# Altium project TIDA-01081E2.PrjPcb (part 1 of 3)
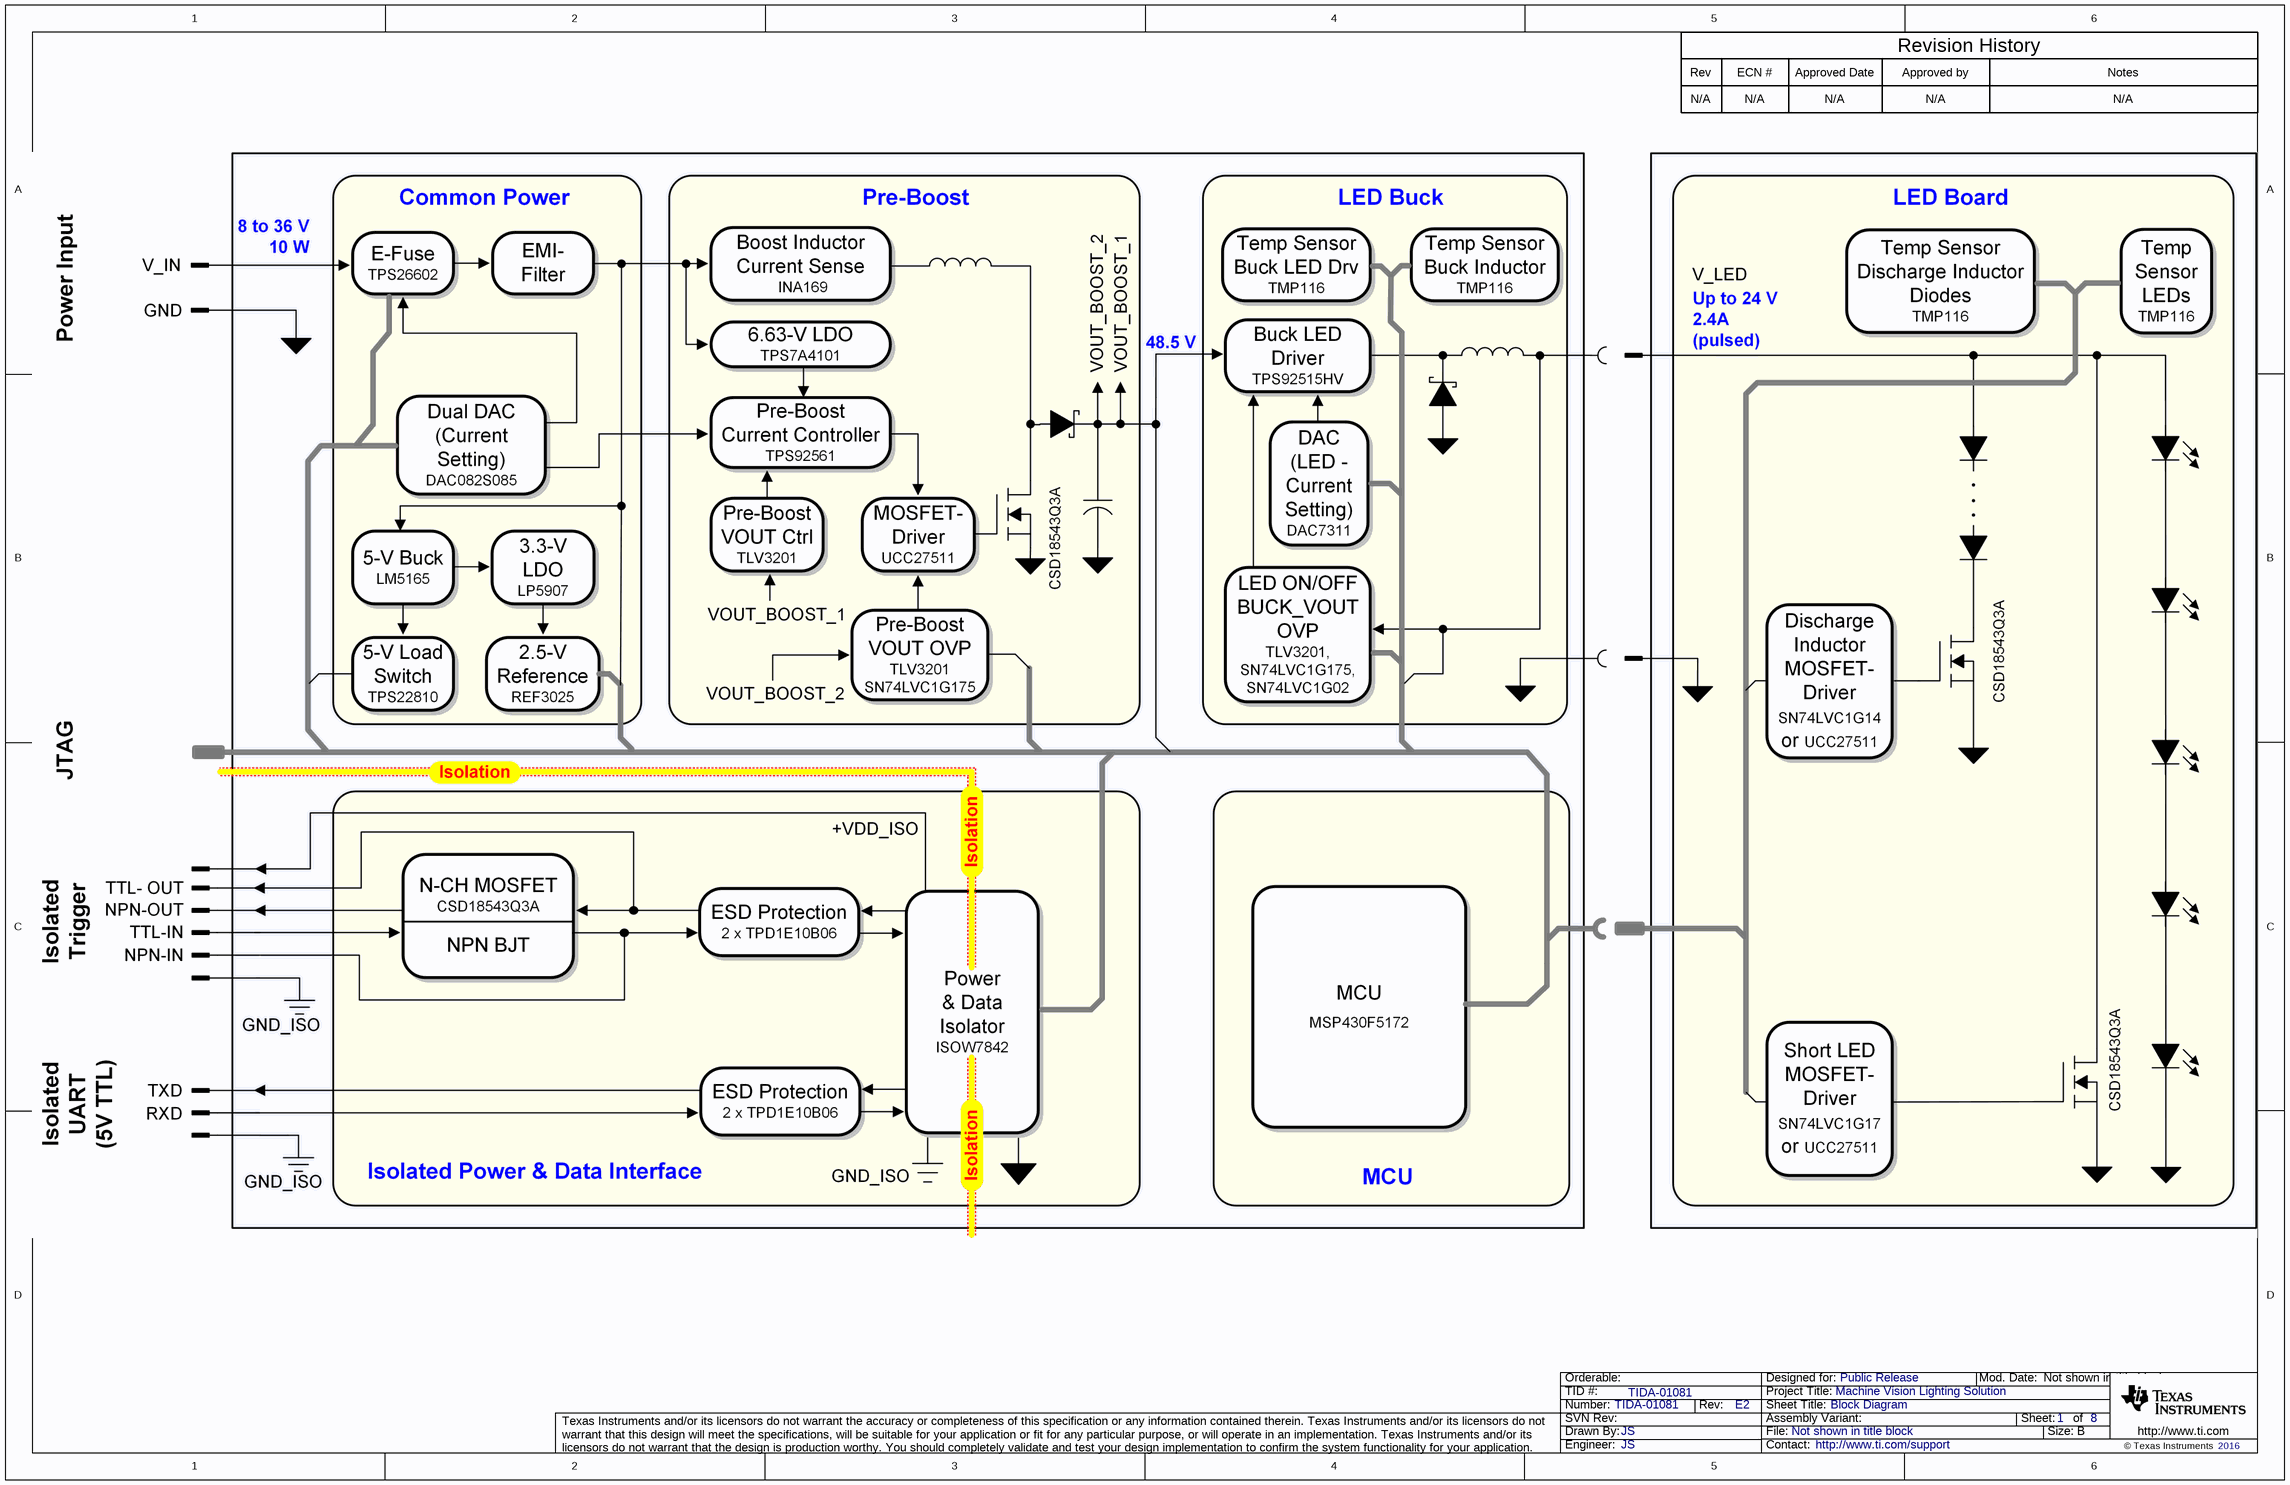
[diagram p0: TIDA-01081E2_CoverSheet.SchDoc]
CopyrightYear: 2016; PCB_Layout: JS; PCB_Rev: E2; PRJ_Customer: Public Release; PRJ_Engineer: JS; PRJ_Number: TIDA-01081; PRJ_Title: Machine Vision Lighting Solution; SCH_Rev: E2; TechSupport: http://www.ti.com/support; TID: TIDA-01081
8 sheets, 411 parts. Net scope: flat (ports and power ports of the same name join across sheets).
Board file: TIDA-01081E2_PCB.PcbDoc
Sheets:
  TIDA-01081E2_CoverSheet.SchDoc
  TIDA-01081E2_CommonPower.SchDoc
  TIDA-01081E2_Controller.SchDoc
  TIDA-01081E2_DigitalIO.SchDoc
  TIDA-01081E2_EVM_Hardware.SchDoc
  TIDA-01081E2_LED_Board.SchDoc
  TIDA-01081E2_LED_Buck.SchDoc
  TIDA-01081E2_Pre-Boost.SchDoc

## Sheet TIDA-01081E2_CoverSheet.SchDoc: Block Diagram
size 431 x 279 mm; Date: Not shown in title block; ApprovedBy: Not shown in title block; CheckedBy: Not shown in title block; Author: Not shown in title block; CompanyName: Not shown in title block; DrawnBy: JS; Engineer: Not shown in title block; Organization: Not shown in title block; Address1: Not shown in title block; Address2: Not shown in title block; Address3: Not shown in title block; Address4: Not shown in title block; DocumentNumber: 1; Revision: Use project parameter SCH_Rev; SheetNumber: 1; SheetTotal: 8; PageSetup: Record=PageOptions¦CenterHorizontal=True¦CenterVertical=True¦PrintScale=1.00¦XCorrection=1.00¦YCorrection=1.00¦PrintKind=0¦BorderSize=5000000¦LeftOffset=0¦BottomOffset=0¦Orientation=2¦PaperLength=1000¦PaperWidth=1000¦Scale=100¦PaperSource=15¦PrintQuality=600¦MediaType=1¦DitherType=10¦PaperKind=Letter¦PrintScaleMode=1

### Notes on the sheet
- Rev
- N/A
- ECN #
- Approved Date
- Approved by
- Revision History
- Notes

## Sheet TIDA-01081E2_CommonPower.SchDoc: Comon Power
size 431 x 279 mm; Date: Not shown in title block; ApprovedBy: Not shown in title block; CheckedBy: Not shown in title block; Author: Not shown in title block; CompanyName: Not shown in title block; DrawnBy: SG; Engineer: Not shown in title block; Organization: Not shown in title block; Address1: Not shown in title block; Address2: Not shown in title block; Address3: Not shown in title block; Address4: Not shown in title block; DocumentNumber: 2; Revision: Use project parameter SCH_Rev; SheetNumber: 2; SheetTotal: 8; PageSetup: Record=PageOptions¦CenterHorizontal=True¦CenterVertical=True¦PrintScale=0.94¦XCorrection=1.00¦YCorrection=1.00¦PrintKind=0¦BorderSize=5000000¦LeftOffset=0¦BottomOffset=0¦Orientation=2¦PaperLength=4200¦PaperWidth=2970¦Scale=100¦PaperSource=7¦PrintQuality=600¦MediaType=1¦DitherType=10¦PrintScaleMode=1¦PaperKind=A3¦PaperIndex=8
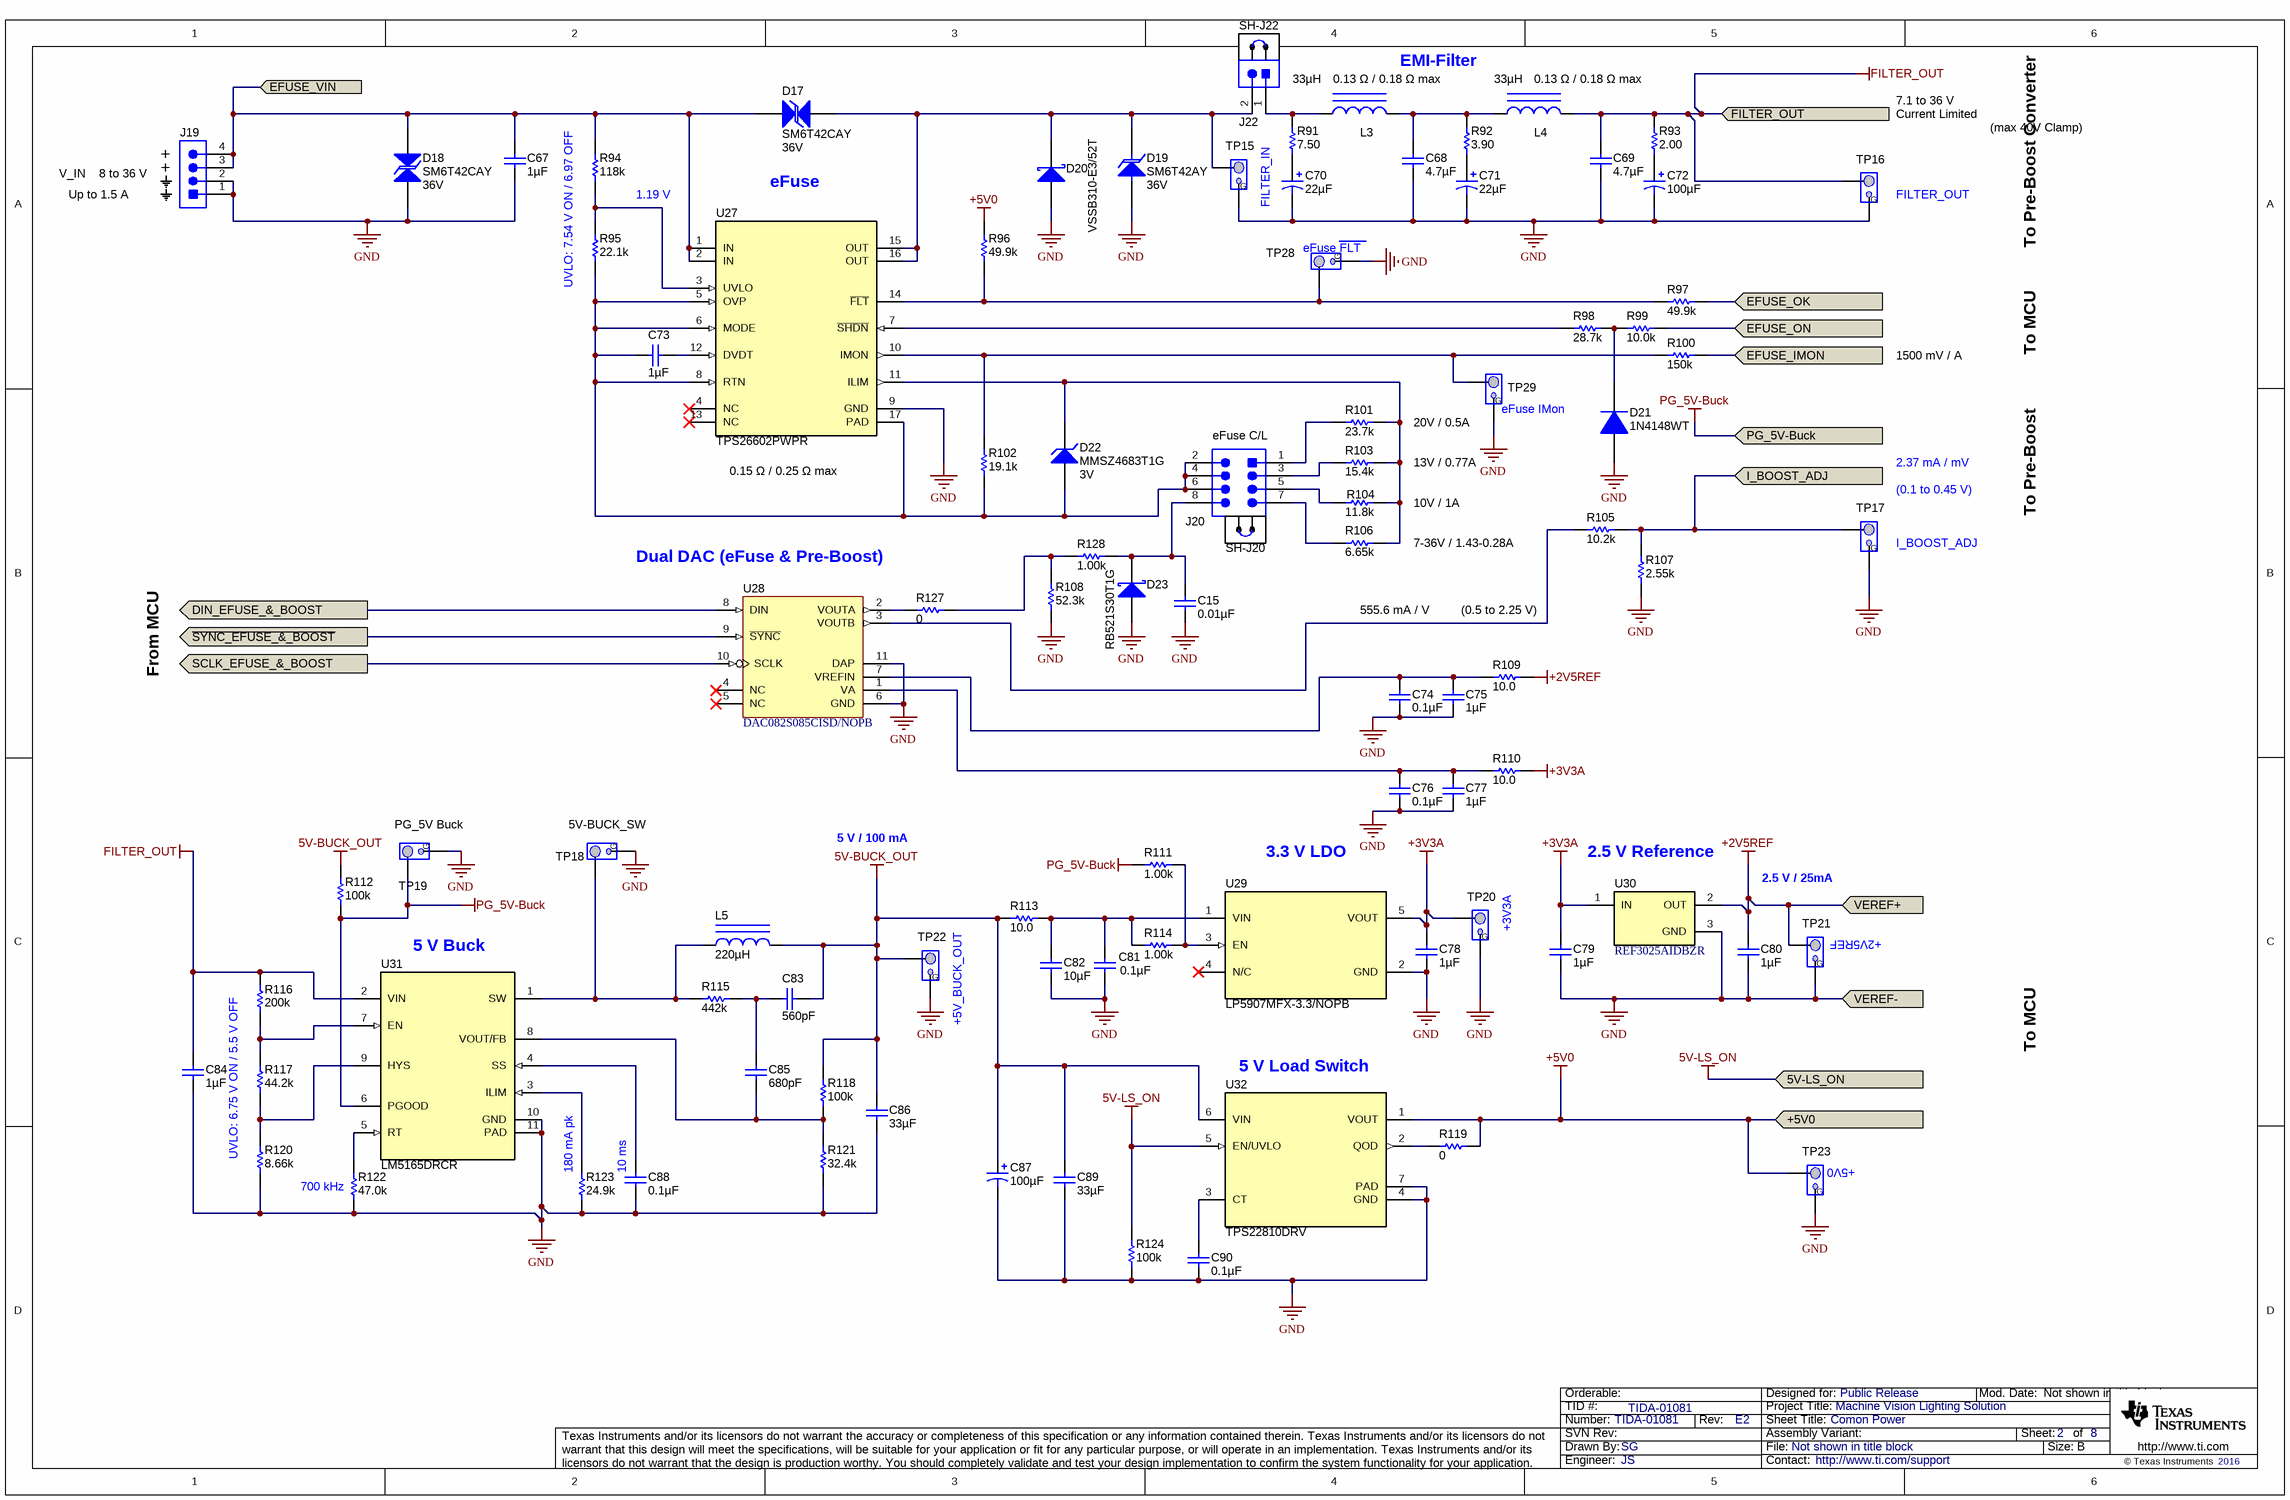
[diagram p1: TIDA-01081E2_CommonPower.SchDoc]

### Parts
C15  ValueDisplayed: 0.01µF  [0402]  (hidden comment: C1005X7R1C103K050BA)
C67  ValueDisplayed: 1µF  [1206_180]  (hidden comment: GRM31CR72A105KA01L)
C68  ValueDisplayed: 4.7µF  [1210_270]  (hidden comment: GRM32ER71K475KE14L)
C69  ValueDisplayed: 4.7µF  [1210_270]  (hidden comment: GRM32ER71K475KE14L)
C70  ValueDisplayed: 22µF  [SM_RADIAL_D8]  (hidden comment: EEE-FK1J220XP)
C71  ValueDisplayed: 22µF  [SM_RADIAL_D8]  (hidden comment: EEE-FK1J220XP)
C72  ValueDisplayed: 100µF  [SM_RADIAL_G]  (hidden comment: EEE-FK1J101P)
C73  ValueDisplayed: 1µF  [0603]  (hidden comment: GRM188R71C105KE15D)
C74  ValueDisplayed: 0.1µF  [0603_HV]  (hidden comment: GCM188R71C104KA37J)
C75  ValueDisplayed: 1µF  [0603]  (hidden comment: GRM188R71C105KE15D)
C76  ValueDisplayed: 0.1µF  [0603_HV]  (hidden comment: GCM188R71C104KA37J)
C77  ValueDisplayed: 1µF  [0603]  (hidden comment: GRM188R71C105KE15D)
C78  ValueDisplayed: 1µF  [0603]  (hidden comment: GRM188R71C105KE15D)
C79  ValueDisplayed: 1µF  [0603]  (hidden comment: GRM188R71C105KE15D)
C80  ValueDisplayed: 1µF  [0603]  (hidden comment: GRM188R71C105KE15D)
C81  ValueDisplayed: 0.1µF  [0603_HV]  (hidden comment: GCM188R71C104KA37J)
C82  ValueDisplayed: 10µF  [0603_120]  (hidden comment: ZRB18AD71A106KE01L)
C83  ValueDisplayed: 560pF  [0603]  (hidden comment: C0603C561J5GACTU)
C84  ValueDisplayed: 1µF  [1206_180]  (hidden comment: GRM31CR72A105KA01L)
C85  ValueDisplayed: 680pF  [0603]  (hidden comment: C0603C681J5GACTU)
C86  ValueDisplayed: 33µF  [1206_180]  (hidden comment: C3216X5R1E336M160AC)
C87  ValueDisplayed: 100µF  [SM_RADIAL_6.3AMM]  (hidden comment: UUD1A101MCL1GS)
C88  ValueDisplayed: 0.1µF  [0603_HV]  (hidden comment: GCM188R71C104KA37J)
C89  ValueDisplayed: 33µF  [1206_180]  (hidden comment: C3216X5R1E336M160AC)
C90  ValueDisplayed: 0.1µF  [0603]  (hidden comment: GRM188R71C104KA01D)
D17  SM6T42CAY  value 36V  [SMB-Bi]
D18  SM6T42CAY  value 36V  [SMB-Bi]
D19  SM6T42AY  value 36V  [SMB]
D20  VSSB310-E3/52T  [SMB]
D21  1N4148WT  [Fairchild_SOD-523F]
D22  MMSZ4683T1G  value 3V  [SOD-123]
D23  RB521S30T1G  [SOD-523]
J19  61300411121  [WURTH_61300411121]  (value not drawn)
J20  PEC04DAAN  [CONN_PEC04DAAN]  (value not drawn)
J22  61300211121  [WURTH_61300211121]  (value not drawn)
L3  ValueDisplayed: 33µH  DCR_ohm: 0.13 Ω / 0.18 Ω max  [CLF7045]  (hidden comment: CLF7045T-330M)
L4  ValueDisplayed: 33µH  DCR_ohm: 0.13 Ω / 0.18 Ω max  [CLF7045]  (hidden comment: CLF7045T-330M)
L5  ValueDisplayed: 220µH  [WE-TPC_4828]  (hidden comment: 744043221)
R91  ValueDisplayed: 7.50  [1206]  (hidden comment: RC1206FR-077R5L)
R92  ValueDisplayed: 3.90  [1206]  (hidden comment: RC1206FR-073R9L)
R93  ValueDisplayed: 2.00  [1206]  (hidden comment: RC1206FR-072RL)
R94  ValueDisplayed: 118k  [0603_HR]  (hidden comment: RR0816P-1183-D-08D)
R95  ValueDisplayed: 22.1k  [0603_HR]  (hidden comment: RR0816P-2212-D-34C)
R96  ValueDisplayed: 49.9k  [0603]  (hidden comment: RC0603FR-0749K9L)
R97  ValueDisplayed: 49.9k  [0603]  (hidden comment: RC0603FR-0749K9L)
R98  ValueDisplayed: 28.7k  [0603]  (hidden comment: RC0603FR-0728K7L)
R99  ValueDisplayed: 10.0k  [0603]  (hidden comment: RC0603FR-0710KL)
R100  ValueDisplayed: 150k  [0603]  (hidden comment: RC0603FR-07150KL)
R101  ValueDisplayed: 23.7k  [0603]  (hidden comment: CRCW060323K7FKEA)
R102  ValueDisplayed: 19.1k  [0603]  (hidden comment: CRCW060319K1FKEA)
R103  ValueDisplayed: 15.4k  [0603]  (hidden comment: CRCW060315K4FKEA)
R104  ValueDisplayed: 11.8k  [0603]  (hidden comment: CRCW060311K8FKEA)
R105  ValueDisplayed: 10.2k  [0603]  (hidden comment: CRCW060310K2FKEA)
R106  ValueDisplayed: 6.65k  [0603]  (hidden comment: CRCW06036K65FKEA)
R107  ValueDisplayed: 2.55k  [0603]  (hidden comment: CRCW06032K55FKEA)
R108  ValueDisplayed: 52.3k  [0603]  (hidden comment: CRCW060352K3FKEA)
R109  value 10.0  [0603]  (hidden comment: CRCW060310R0FKEA)
R110  value 10.0  [0603]  (hidden comment: CRCW060310R0FKEA)
R111  ValueDisplayed: 1.00k  [0603]  (hidden comment: RC0603FR-071KL)
R112  ValueDisplayed: 100k  [0603]  (hidden comment: RC0603FR-07100KL)
R113  value 10.0  [0603]  (hidden comment: CRCW060310R0FKEA)
R114  ValueDisplayed: 1.00k  [0603]  (hidden comment: RC0603FR-071KL)
R115  ValueDisplayed: 442k  [0603]  (hidden comment: RC0603FR-07442KL)
R116  ValueDisplayed: 200k  [0603]  (hidden comment: RT0603BRD07200KL)
R117  ValueDisplayed: 44.2k  [0603_HR]  (hidden comment: RR0816P-4422-D-63C)
R118  ValueDisplayed: 100k  [0603_HR]  (hidden comment: RR0816P-104-D)
R119  ValueDisplayed: 0  [0603]  (hidden comment: RC0603JR-070RL)
R120  ValueDisplayed: 8.66k  [0603_HR]  (hidden comment: RR0816P-8661-D-91H)
R121  ValueDisplayed: 32.4k  [0603]  (hidden comment: RT0603DRE0732K4L)
R122  ValueDisplayed: 47.0k  [0603]  (hidden comment: RC0603FR-0747KL)
R123  ValueDisplayed: 24.9k  [0603]  (hidden comment: CRCW060324K9FKEA)
R124  ValueDisplayed: 100k  [0603]  (hidden comment: RC0603FR-07100KL)
R127  ValueDisplayed: 0  [0603]  (hidden comment: RC0603JR-070RL)
R128  ValueDisplayed: 1.00k  [0603]  (hidden comment: CRCW06031K00FKEA)
SH-J20  969102-0000-DA  [SNT-100-BK-G]  (value not drawn)
SH-J22  969102-0000-DA  [SNT-100-BK-G]  (value not drawn)
TP15  TESTPOINT_PIGTAIL  [TESTPOINT_PIGTAIL]  (value not drawn)  (no BOM)
TP16  TESTPOINT_PIGTAIL  [TESTPOINT_PIGTAIL]  (value not drawn)  (no BOM)
TP17  TESTPOINT_PIGTAIL  [TESTPOINT_PIGTAIL]  (value not drawn)  (no BOM)
TP18  TESTPOINT_PIGTAIL  [TESTPOINT_PIGTAIL]  (value not drawn)  (no BOM)
TP19  TESTPOINT_PIGTAIL  [TESTPOINT_PIGTAIL]  (value not drawn)  (no BOM)
TP20  TESTPOINT_PIGTAIL  [TESTPOINT_PIGTAIL]  (value not drawn)  (no BOM)
TP21  TESTPOINT_PIGTAIL  [TESTPOINT_PIGTAIL]  (value not drawn)  (no BOM)
TP22  TESTPOINT_PIGTAIL  [TESTPOINT_PIGTAIL]  (value not drawn)  (no BOM)
TP23  TESTPOINT_PIGTAIL  [TESTPOINT_PIGTAIL]  (value not drawn)  (no BOM)
TP28  TESTPOINT_PIGTAIL  [TESTPOINT_PIGTAIL]  (value not drawn)  (no BOM)
TP29  TESTPOINT_PIGTAIL  [TESTPOINT_PIGTAIL]  (value not drawn)  (no BOM)
U27  TPS26602PWPR  [PWP0016H_N]
U28  DAC082S085CISD/NOPB  [SDA10A]
U29  LP5907MFX-3.3/NOPB  [DBV0005A_N]
U30  REF3025AIDBZR  [DBZ0003A_N]
U31  LM5165DRCR  [DRC0010J]
U32  TPS22810DRV  [DRV0006A]

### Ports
5V-LS_ON, +5V0, DIN_EFUSE_&_BOOST, EFUSE_IMON, EFUSE_OK, EFUSE_ON, EFUSE_VIN, FILTER_OUT, I_BOOST_ADJ, PG_5V-Buck, SCLK_EFUSE_&_BOOST, VEREF+, VEREF-, ~{SYNC_EFUSE_&_BOOST}

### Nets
5V-BUCK_OUT: C83.1 C86.1 C87.1(+) C89.1 L5.2 R112.2 R113.2 R118.2 TP22.1 U32.6(VIN)
5V-LS_ON: R124.2 U32.5(EN/UVLO) ; port 5V-LS_ON
+2V5REF: C80.1 R109.1 TP21.1 U30.2(OUT) ; port VEREF+
+3V3A: C78.1 C79.1 R110.1 TP20.1 U29.5(VOUT) U30.1(IN)
+5V0: R96.2 R119.2 TP23.1 U32.1(VOUT) ; port +5V0
FILTER_OUT: C69.1 C84.1 L4.2 R93.2 R116.2 TP16.1 U31.2(VIN) ; port FILTER_OUT
GND: C15.2 C67.2 C68.2 C69.2 C70.2(-) C71.2(-) C72.2(-) C74.1 C75.1 C76.1 C77.1 C78.2 C79.2 C80.2 C81.1 C82.2 C84.2 C86.2 C87.2(-) C88.1 C89.2 C90.2 D18.1 D19.2(A) D20.2(A) D21.2(A) D23.2(A) J19.1 J19.2 R107.1 R108.1 R120.1 R121.1 R122.1 R123.1 R124.1 TP15.2 TP16.2 TP17.2 TP18.2 TP19.2 TP20.2 TP21.2 TP22.2 TP23.2 TP28.2 TP29.2 U27.9(GND) U28.6(GND) U28.11(DAP) U29.2(GND) U30.3(GND) U31.10(GND) U31.11(PAD) U32.4(GND) U32.7(PAD) ; port VEREF-
PG_5V-Buck: R111.1 R112.1 TP19.1 U31.6(PGOOD) ; port PG_5V-Buck
~{SYNC_EFUSE_&_BOOST}: U28.9(~{SYNC}) ; port ~{SYNC_EFUSE_&_BOOST}
DIN: U28.8(DIN) ; port DIN_EFUSE_&_BOOST
EFUSE_IMON: R100.2 ; port EFUSE_IMON
EFUSE_OK: R97.2 ; port EFUSE_OK
EFUSE_ON: R99.1 ; port EFUSE_ON
EFUSE_VIN: C67.1 D17.1 D18.2 J19.3 J19.4 R94.2 U27.1(IN) U27.2(IN) ; port EFUSE_VIN
I_BOOST_ADJ: R105.2 R107.2 TP17.1 ; port I_BOOST_ADJ
SCLK: U28.10(SCLK) ; port SCLK_EFUSE_&_BOOST
NetC15_1: C15.1 D23.1(K) J20.8 R128.2
NetC68_1: C68.1 L3.2 L4.1 R92.2
NetC70_1: C70.1(+) R91.1
NetC71_1: C71.1(+) R92.1
NetC72_1: C72.1(+) R93.1
NetC73_1: C73.1 D22.2(A) J20.2 J20.4 J20.6 R95.1 R102.1 U27.5(OVP) U27.6(MODE) U27.8(RTN) U27.17(PAD)
NetC73_2: C73.2 U27.12(DVDT)
NetC74_2: C74.2 C75.2 R109.2 U28.7(VREFIN)
NetC76_2: C76.2 C77.2 R110.2 U28.1(VA)
NetC81_2: C81.2 C82.1 R113.1 R114.1 U29.1(VIN)
NetC83_2: C83.2 C85.1 R115.2
NetC85_2: C85.2 R118.1 R121.2 U31.8(VOUT/FB)
NetC88_2: C88.2 U31.4(SS)
NetC90_1: C90.1 U32.3(CT)
NetD17_2: D17.2 D19.1(K) D20.1(K) J22.2 TP15.1 U27.15(OUT) U27.16(OUT)
NetD21_1: D21.1(K) R98.2 R99.2
NetD22_1: D22.1(K) R101.1 R103.2 R104.2 R106.1 U27.11(ILIM)
NetJ20_1: J20.1 R101.2
NetJ20_3: J20.3 R103.1
NetJ20_5: J20.5 R104.1
NetJ20_7: J20.7 R106.2
NetJ22_1: J22.1 L3.1 R91.2
NetL5_1: L5.1 R115.1 TP18.1 U31.1(SW)
NetR94_1: R94.1 R95.2 U27.3(UVLO)
NetR96_1: R96.1 R97.1 TP28.1 U27.14(~{FLT})
NetR98_1: R98.1 U27.7(~{SHDN})
NetR100_1: R100.1 R102.2 TP29.1 U27.10(IMON)
NetR105_1: R105.1 U28.3(VOUTB)
NetR108_2: R108.2 R127.2 R128.1
NetR111_2: R111.2 R114.2 U29.3(EN)
NetR116_1: R116.1 R117.2 U31.7(EN)
NetR117_1: R117.1 R120.2 U31.9(HYS)
NetR119_1: R119.1 U32.2(QOD)
NetR122_2: R122.2 U31.5(RT)
NetR123_2: R123.2 U31.3(ILIM)
NetR127_1: R127.1 U28.2(VOUTA)

Not connected (* = marked no-connect by the designer): U27 4(NC)* 13(NC)*; U28 4(NC)* 5(NC)*; U29 4(N/C)*

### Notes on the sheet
- EMI-Filter
- 7.1 to 36 V
- Current Limited
- V_IN
- (near J19) 8 to 36 V
- (near J19) +
- eFuse
- (max 40V Clamp)
- Up to 1.5 A
- 1.19 V
- FILTER_IN
- (near TP28) eFuse FLT
- (near TP16) FILTER_OUT
- To Pre-Boost Converter
- UVLO: 7.54 V ON / 6.97 OFF
- 1500 mV / A
- To MCU
- (near J20) eFuse C/L
- (near TP29) 20V / 0.5A
- (near TP29) eFuse IMon
- (near U27) 0.15 Ω / 0.25 Ω max
- Text
- (near R103) Text
- 13V / 0.77A
- 10V / 1A
- 2.37 mA / mV
- (near TP17) (0.1 to 0.45 V)
- To Pre-Boost
- Dual DAC (eFuse & Pre-Boost)
- 7-36V / 1.43-0.28A
- (near TP17) I_BOOST_ADJ
- 555.6 mA / V         (0.5 to 2.25 V)
- From MCU
- (near TP19) PG_5V Buck
- (near TP18) 5V-BUCK_SW
- 5 V / 100 mA
- 3.3 V LDO
- (near U30) 2.5 V Reference
- 2.5 V / 25mA
- (near U31) 5 V Buck
- (near TP20) +3V3A
- (near TP21) +2V5REF
- (near TP22) +5V_BUCK_OUT
- (near U32) 5 V Load Switch
- UVLO: 6.75 V ON / 5.5 V OFF
- (near R122) 700 kHz
- (near R123) 180 mA pk
- (near C88) 10 ms
- (near TP23) +5V0

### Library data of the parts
C15 = C1005X7R1C103K050BA: CAP, CERM, 0.01 µF, 16 V, +/- 10%, X7R, 0402; Manufacturer: TDK; Polarized: N; CompType: Capacitor; Value: 0.01uF; U/M: EA; Cap_F: 0.00000001; Tolerance_%: 10; ESR_ohm: 0.0623; Value1: 0.0623 ohm; VDC_V: 16; Value2: 16V; TaMin_C: -55; TaMax_C: 125; SizeArea_mm2: 0.5; SizeAreaWB_mm2: 3; SizeX_mm: 1; SizeZ_mm: 0.6; AEC Category: Q200; Green_Lifecycle: NRND; Green_REACh: Passed
C67 C84 = GRM31CR72A105KA01L: CAP, CERM, 1 µF, 100 V, +/- 10%, X7R, 1206; Manufacturer: MuRata; Polarized: N; CompType: Capacitor; Value: 1uF; U/M: EA; Cap_F: 0.000001; Tolerance_%: 10; Value1: Unknown; VDC_V: 100; Value2: 100V; TaMin_C: -55; TaMax_C: 125; Cap_Case: 1206; SizeArea_mm2: 5.12; SizeAreaWB_mm2: 10.92; SizeX_mm: 3.2; SizeY_mm: 1.6; SizeZ_mm: 1.8; AEC Category: Q200; Green_Lifecycle: Active; Green_REACh: Passed
C68 C69 = GRM32ER71K475KE14L: CAP, CERM, 4.7 µF, 80 V, +/- 10%, X7R, 1210; Manufacturer: MuRata; Polarized: N; CompType: Capacitor; Value: 4.7uF; U/M: EA; Cap_F: 0.0000047; Tolerance_%: 10; Value1: Unknown; VDC_V: 80; Value2: 80V; TaMin_C: -55; TaMax_C: 125; Cap_Case: 1210; SizeArea_mm2: 8; SizeAreaWB_mm2: 14.7; SizeX_mm: 3.2; SizeY_mm: 2.5; SizeZ_mm: 2.7; AEC Category: Q200
C70 C71 = EEE-FK1J220XP: CAP, AL, 22 µF, 63 V, +/- 20%, 1.2 ohm, AEC-Q200 Grade 2, SMD; Manufacturer: Panasonic; Polarized: Y; CompType: Capacitor; Value: 22uF; U/M: EA; Cap_F: 0.000022; Tolerance_%: 20; Value1: 1.2 ohm; VDC_V: 63; Value2: 63V; ESR_ohm: 1.2; IRMS_A: 0.12; TaMin_C: -55; TaMax_C: 105; Cap_Case: D8; SizeAreaWB_mm2: 84.28; SizeArea_mm2: 51.48; SizeX_mm: 7.8; SizeY_mm: 6.6; SizeZ_mm: 7.7; AEC Category: Q200; AEC Grade: 2; Green_Lifecycle: Active; Green_REACh: Passed
C72 = EEE-FK1J101P: CAP, AL, 100 µF, 63 V, +/- 20%, 0.35 ohm, AEC-Q200 Grade 2, SMD; Manufacturer: Panasonic; Polarized: Y; CompType: Capacitor; Value: 100uF; U/M: EA; Cap_F: 0.0001; Tolerance_%: 20; VDC_V: 63; Value2: 63V; ESR_ohm: 0.35; IRMS_A: 0.4; TaMin_C: -55; TaMax_C: 105; Cap_Case: G; SizeAreaWB_mm2: 172.2; SizeArea_mm2: 123.6; SizeX_mm: 12; SizeY_mm: 10.3; SizeZ_mm: 10.2; AEC Category: Q200; AEC Grade: 2
C73 C75 C77-C80 = GRM188R71C105KE15D: CAP, CERM, 1 µF, 16 V, +/- 10%, X7R, 0603; Manufacturer: MuRata; Polarized: N; CompType: Capacitor; Value: 1uF; U/M: EA; Cap_F: 0.000001; Tolerance_%: 10; Value1: Unknown; VDC_V: 16; Value2: 16V; TaMin_C: -55; TaMax_C: 125; SizeArea_mm2: 1.28; SizeAreaWB_mm2: 4.68; SizeX_mm: 1.6; SizeY_mm: 0.8; SizeZ_mm: 1; AEC Category: Q200
C74 C76 C81 C88 = GCM188R71C104KA37J: CAP, CERM, 0.1 µF, 16 V, +/- 10%, X7R, 0603_095; Manufacturer: MuRata; Polarized: N; CompType: Capacitor; Value: 0.1uF; U/M: EA; Cap_F: 0.0000001; Tolerance_%: 10; Value1: Unknown; VDC_V: 16; Value2: 16V; TaMin_C: -55; TaMax_C: 125; Cap_Case: 0603
C82 = ZRB18AD71A106KE01L: CAP, CERM, 10 µF, 10 V, +/- 10%, X7T, 0603; Manufacturer: MuRata; Polarized: N; CompType: Capacitor; Value: 10uF; U/M: EA; Cap_F: 0.00001; Tolerance_%: 10; Value1: Unknown; Value2: 10V; TaMin_C: -55; TaMax_C: 125; Cap_Case: 0603; SizeArea_mm2: 1.28; SizeAreaWB_mm2: 4.68; SizeX_mm: 1.6; SizeY_mm: 0.8; SizeZ_mm: 1.2; AEC Category: Q200
C83 = C0603C561J5GACTU: CAP, CERM, 560 pF, 50 V, +/- 5%, C0G/NP0, 0603; Manufacturer: Kemet; Polarized: N; CompType: Capacitor; Value: 560pF; U/M: EA; Cap_F: 0.00000000056; Tolerance_%: 5; Value1: Unknown; VDC_V: 50; Value2: 50V; TaMin_C: -55; TaMax_C: 125; SizeArea_mm2: 1.28; SizeAreaWB_mm2: 4.68; SizeX_mm: 1.6; SizeY_mm: 0.8; SizeZ_mm: 1; AEC Category: Q200; Green_Lifecycle: Active; Green_REACh: Passed
C85 = C0603C681J5GACTU: CAP, CERM, 680 pF, 50 V,+/- 5%, C0G/NP0, 0603; Manufacturer: Kemet; Polarized: N; CompType: Capacitor; Value: 680pF; U/M: EA; Cap_F: 0.00000000068; Tolerance_%: 5; VDC_V: 50; Value2: 50V; TaMin_C: -55; TaMax_C: 125; SizeArea_mm2: 1.28; SizeAreaWB_mm2: 4.68; SizeX_mm: 1.6; SizeY_mm: 0.8; SizeZ_mm: 1; AEC Category: Q200; Green_Lifecycle: Not Set; Green_REACh: Incomplete
C86 C89 = C3216X5R1E336M160AC: CAP, CERM, 33 µF, 25 V, +/- 20%, X5R, 1206; Manufacturer: TDK; Polarized: N; CompType: Capacitor; Value: 33uF; U/M: EA; Cap_F: 0.000033; Tolerance_%: 20; ESR_ohm: 0.002648; Value1: 0.002648 ohm; VDC_V: 25; Value2: 25V; IRMS_A: 4.45864; TaMin_C: -55; TaMax_C: 85; Cap_Case: 1206; SizeArea_mm2: 5.12; SizeAreaWB_mm2: 10.92; SizeX_mm: 3.2; SizeY_mm: 1.6; SizeZ_mm: 1.8; AEC Category: Q200; Green_Lifecycle: Active; Green_REACh: Passed
C87 = UUD1A101MCL1GS: CAP, AL, 100 µF, 10 V, +/- 20%, 0.44 ohm, SMD; Manufacturer: Nichicon; Polarized: Y; CompType: Capacitor; Value: 100uF; U/M: EA; Cap_F: 0.0001; Tolerance_%: 20; VDC_V: 10; Value2: 10V; ESR_ohm: 0.44; IRMS_A: 0.23; TaMin_C: -55; TaMax_C: 105; Cap_Case: 6.3x5.8; SizeAreaWB_mm2: 79.98; SizeArea_mm2: 48.18; SizeX_mm: 7.3; SizeY_mm: 6.6; SizeZ_mm: 6; AEC Category: Q200
C90 = GRM188R71C104KA01D: CAP, CERM, 0.1 µF, 16 V, +/- 10%, X7R, 0603; Manufacturer: MuRata; Polarized: N; CompType: Capacitor; Value: 0.1uF; U/M: EA; Cap_F: 0.0000001; Tolerance_%: 10; Value1: Unknown; VDC_V: 16; Value2: 16V; TaMin_C: -55; TaMax_C: 125; SizeArea_mm2: 1.28; SizeAreaWB_mm2: 4.68; SizeX_mm: 1.6; SizeY_mm: 0.8; SizeZ_mm: 1; AEC Category: Q200; Green_Lifecycle: Active; Green_REACh: Passed
D17 D18 = SM6T42CAY: Diode, TVS, Bi, 36 V, 76 Vc, AEC-Q101, SMB; Manufacturer: STMicroelectronics; U/M: EA; Vr_V: 36; Value1: W; AEC Category: Q101; AEC Qualified: Y
D19 = SM6T42AY: Diode, TVS, Uni, 36 V, AEC-Q101, SMB; Manufacturer: Semtech; U/M: EA; Vr_V: 36; Value1: W; SizeAreaWB_mm2: 44.156; SizeArea_mm2: 21.336; SizeX_mm: 5.6; SizeY_mm: 3.81; SizeZ_mm: 2.6; AEC Category: Q101; AEC Qualified: Y
D20 = VSSB310-E3/52T: Diode, Schottky, 100 V, 1.9 A, SMB; Manufacturer: Vishay-Semiconductor; U/M: EA; Vf_V: 0.56; Value: 100V; Value1: 1.9A; Value2: 0.56V; Io_A: 1.9; Vr_V: 100; TJmax_C: 150; SizeAreaWB_mm2: 44.156; SizeArea_mm2: 21.336; SizeX_mm: 5.6; SizeY_mm: 3.81; SizeZ_mm: 2.6; AEC Category: Q101; AEC Qualified: N
D21 = 1N4148WT: Diode, Switching, 75 V, 0.3 A, SOD-523F; Manufacturer: Fairchild Semiconductor; U/M: EA; Value: 75V; Value1: 0.3A; Io_A: 0.3; Vr_V: 75; TJmax_C: 150; SizeAreaWB_mm2: 4.68; SizeArea_mm2: 1.28; SizeX_mm: 1.6; SizeY_mm: 0.8; SizeZ_mm: 0.7; AEC Category: Q101; Green_Lifecycle: Not Set; Green_REACh: Incomplete
D22 = MMSZ4683T1G: Diode, Zener, 3 V, 500 mW, SOD-123; Manufacturer: ON Semiconductor; SymbolCreator: a0412235; U/M: EA; Power_W: 0.5; Vz_V: 3; Value1: 0.5W; RJA_CperW: 340; SizeAreaWB_mm2: 13.095; SizeArea_mm2: 6.545; SizeX_mm: 3.85; SizeY_mm: 1.7; SizeZ_mm: 1.35; AEC Category: Q101
D23 = RB521S30T1G: Diode, Schottky, 30 V, 0.2 A, AEC-Q101, SOD-523; Manufacturer: ON Semiconductor; U/M: EA; Vf_V: 0.5; Value: 30V; Value1: 0.2A; Value2: 0.5V; Io_A: 0.2; Vr_V: 30; TJmax_C: 125; SizeAreaWB_mm2: 5.13; SizeArea_mm2: 1.53; SizeX_mm: 1.7; SizeY_mm: 0.9; SizeZ_mm: 0.65; AEC Category: Q101; AEC Qualified: Y; Green_Lifecycle: Not Set; Green_REACh: Incomplete
J19 = 61300411121: Header, 2.54 mm, 4x1, Gold, TH; Manufacturer: Wurth Elektronik; SymbolCreator: a0412235
J20 = PEC04DAAN: Header, 100mil, 4x2, Tin, TH; Manufacturer: Sullins Connector Solutions; SymbolCreator: a0411947; Pitch_mm: 2.54; Gender: Male; Shrouded: N; Row_Count: 2; Current_A: 3; Voltage_V: 1800; Cert_UL: Y; Green_Lifecycle: Not Set; Green_REACh: Incomplete
J22 = 61300211121: Header, 2.54 mm, 2x1, Gold, TH; Manufacturer: Wurth Elektronik; SymbolCreator: a0412235
L3 L4 = CLF7045T-330M: Inductor, Shielded, Ferrite, 33 µH, 1.55 A, 0.13 ohm, SMD; Manufacturer: TDK; Value: 33uH; Ind_H: 33.0E-6; Imax_A: 1.55; Irms: 1.4A @ 30C rise; Isat: 1.55A @ 10% inductance drop; Value2: 1.55A; SizeAreaWB_mm2: 85.54; SizeArea_mm2: 52.54; SizeX_mm: 7.4; SizeY_mm: 7.1; SizeZ_mm: 4.8; AEC Category: Q200
L5 = 744043221: Inductor, Shielded Drum Core, Metal Composite, 220 µH, 0.2 A, 1.008 ohm, SMD; Manufacturer: Wurth Elektronik; Value: 220uH; Ind_H: 220.0E-6; Imax_A: 0.2; Irms: 0.34A @ 30C rise; Isat: 0.2A @ 35% inductance drop; DCR_ohm: 1.008; Value2: 0.2A; SizeAreaWB_mm2: 33.64; SizeArea_mm2: 23.04; SizeX_mm: 4.8; SizeZ_mm: 3; AEC Category: Q200; Green_Lifecycle: Active; Green_REACh: Passed
R91 = RC1206FR-077R5L: RES, 7.50, 1%, 0.25 W, 1206; Manufacturer: Yageo America; CompType: Resistor; Value: 7.50; Res_ohm: 7.5; Value_Code: 7R50; Tolerance_%: 1; Power_W: 0.25; Value2: 0.25W; VDC_V: 200; TempCo: 200 ppm/C; SizeArea_mm2: 5.12; SizeX_mm: 3.2; SizeY_mm: 1.6; SizeZ_mm: 1.35; EIA_Code: E96; U/M: EA; AEC Category: Q200; Green_Lifecycle: Active; Green_REACh: Passed
R92 = RC1206FR-073R9L: RES, 3.90, 1%, 0.25 W, 1206; Manufacturer: Yageo America; CompType: Resistor; Value: 3.90; Res_ohm: 3.9; Value_Code: 3R90; Tolerance_%: 1; Power_W: 0.25; Value2: 0.25W; VDC_V: 200; TempCo: 200 ppm/C; SizeArea_mm2: 5.12; SizeX_mm: 3.2; SizeY_mm: 1.6; SizeZ_mm: 1.35; U/M: EA; AEC Category: Q200; Green_Lifecycle: Active; Green_REACh: Passed
R93 = RC1206FR-072RL: RES, 2.00, 1%, 0.25 W, 1206; Manufacturer: Yageo America; CompType: Resistor; Value: 2.00; Res_ohm: 2; Value_Code: 2R00; Tolerance_%: 1; Power_W: 0.25; Value2: 0.25W; VDC_V: 200; TempCo: 200 ppm/C; SizeArea_mm2: 5.12; SizeX_mm: 3.2; SizeY_mm: 1.6; SizeZ_mm: 1.35; EIA_Code: E96; U/M: EA; AEC Category: Q200
R94 = RR0816P-1183-D-08D: RES, 118 k, 0.5%, 0.0625 W, 0603; Manufacturer: Susumu Co Ltd; CompType: Resistor; Value: 118k; Res_ohm: 118000; Tolerance_%: 0.5; Power_W: 0.0625; VDC_V: 75; TempCo: 25 ppm/C; SizeArea_mm2: 1.3175; SizeX_mm: 1.55; SizeY_mm: 0.85; EIA_Code: E192; U/M: EA; AEC Category: Q200; AEC Qualified: N
R95 = RR0816P-2212-D-34C: RES, 22.1 k, 0.5%, 0.0625 W, 0603; Manufacturer: Susumu Co Ltd; CompType: Resistor; Value: 22.1k; Res_ohm: 22100; Value_Code: 22k1; Tolerance_%: 0.5; Power_W: 0.0625; VDC_V: 75; TempCo: 25 ppm/C; SizeArea_mm2: 1.3175; SizeX_mm: 1.55; SizeY_mm: 0.85; EIA_Code: E192; U/M: EA; AEC Category: Q200; AEC Qualified: N
R96 R97 = RC0603FR-0749K9L: RES, 49.9 k, 1%, 0.1 W, 0603; Manufacturer: Yageo America; CompType: Resistor; Value: 49.9k; Res_ohm: 49900; Value_Code: 49k9; Tolerance_%: 1; Power_W: 0.1; Value2: 0.1W; VDC_V: 150; TempCo: 200 ppm/C; SizeArea_mm2: 1.28; SizeX_mm: 1.6; SizeY_mm: 0.8; EIA_Code: E96; U/M: EA; AEC Category: Q200; Green_Lifecycle: Active; Green_REACh: Passed
R98 = RC0603FR-0728K7L: RES, 28.7 k, 1%, 0.1 W, 0603; Manufacturer: Yageo America; CompType: Resistor; Value: 28.7k; Res_ohm: 28700; Value_Code: 28k7; Tolerance_%: 1; Power_W: 0.1; Value2: 0.1W; VDC_V: 150; TempCo: 200 ppm/C; SizeArea_mm2: 1.28; SizeX_mm: 1.6; SizeY_mm: 0.8; EIA_Code: E96; U/M: EA; AEC Category: Q200
R99 = RC0603FR-0710KL: RES, 10.0 k, 1%, 0.1 W, 0603; Manufacturer: Yageo America; CompType: Resistor; Value: 10.0k; Res_ohm: 10000; Value_Code: 10k0; Tolerance_%: 1; Power_W: 0.1; Value2: 0.1W; VDC_V: 150; TempCo: 200 ppm/C; SizeArea_mm2: 1.28; SizeX_mm: 1.6; SizeY_mm: 0.8; EIA_Code: E96; U/M: EA; AEC Category: Q200
R100 = RC0603FR-07150KL: RES, 150 k, 1%, 0.1 W, 0603; Manufacturer: Yageo America; CompType: Resistor; Value: 150k; Res_ohm: 150000; Tolerance_%: 1; Power_W: 0.1; Value2: 0.1W; VDC_V: 150; TempCo: 200 ppm/C; SizeArea_mm2: 1.28; SizeX_mm: 1.6; SizeY_mm: 0.8; EIA_Code: E96; U/M: EA; AEC Category: Q200; Green_Lifecycle: Active; Green_REACh: Passed
R101 = CRCW060323K7FKEA: RES, 23.7 k, 1%, 0.1 W, 0603; Manufacturer: Vishay-Dale; CompType: Resistor; Value: 23.7k; Res_ohm: 23700; Value_Code: 23k7; Tolerance_%: 1; Power_W: 0.1; Value2: 0.1W; VDC_V: 75; TempCo: 100 ppm/C; SizeArea_mm2: 1.28; SizeX_mm: 1.6; SizeY_mm: 0.8; EIA_Code: E96; U/M: EA; AEC Category: Q200
R102 = CRCW060319K1FKEA: RES, 19.1 k, 1%, 0.1 W, 0603; Manufacturer: Vishay-Dale; CompType: Resistor; Value: 19.1k; Res_ohm: 19100; Value_Code: 19k1; Tolerance_%: 1; Power_W: 0.1; Value2: 0.1W; VDC_V: 75; TempCo: 100 ppm/C; SizeArea_mm2: 1.28; SizeX_mm: 1.6; SizeY_mm: 0.8; EIA_Code: E96; U/M: EA; AEC Category: Q200; Green_Lifecycle: Active; Green_REACh: Passed
R103 = CRCW060315K4FKEA: RES, 15.4 k, 1%, 0.1 W, 0603; Manufacturer: Vishay-Dale; CompType: Resistor; Value: 15.4k; Res_ohm: 15400; Value_Code: 15k4; Tolerance_%: 1; Power_W: 0.1; Value2: 0.1W; VDC_V: 75; TempCo: 100 ppm/C; SizeArea_mm2: 1.28; SizeX_mm: 1.6; SizeY_mm: 0.8; EIA_Code: E96; U/M: EA; AEC Category: Q200; Green_Lifecycle: Active; Green_REACh: Passed
R104 = CRCW060311K8FKEA: RES, 11.8 k, 1%, 0.1 W, 0603; Manufacturer: Vishay-Dale; CompType: Resistor; Value: 11.8k; Res_ohm: 11800; Value_Code: 11k8; Tolerance_%: 1; Power_W: 0.1; Value2: 0.1W; VDC_V: 75; TempCo: 100 ppm/C; SizeArea_mm2: 1.28; SizeX_mm: 1.6; SizeY_mm: 0.8; EIA_Code: E96; U/M: EA; AEC Category: Q200; Green_Lifecycle: Active; Green_REACh: Passed
R105 = CRCW060310K2FKEA: RES, 10.2 k, 1%, 0.1 W, 0603; Manufacturer: Vishay-Dale; CompType: Resistor; Value: 10.2k; Res_ohm: 10200; Value_Code: 10k2; Tolerance_%: 1; Power_W: 0.1; Value2: 0.1W; VDC_V: 75; TempCo: 100 ppm/C; SizeArea_mm2: 1.28; SizeX_mm: 1.6; SizeY_mm: 0.8; EIA_Code: E96; U/M: EA; AEC Category: Q200; Green_Lifecycle: Active; Green_REACh: Passed
R106 = CRCW06036k65FKEA: RES, 6.65 k, 1%, 0.1 W, 0603; Manufacturer: Vishay-Dale; CompType: Resistor; Value: 6.65k; Res_ohm: 6650; Value_Code: 6k65; Tolerance_%: 1; Power_W: 0.1; Value2: 0.1W; VDC_V: 75; TempCo: 100 ppm/C; SizeArea_mm2: 1.28; SizeX_mm: 1.6; SizeY_mm: 0.8; EIA_Code: E96; U/M: EA; AEC Category: Q200
R107 = CRCW06032K55FKEA: RES, 2.55 k, 1%, 0.1 W, 0603; Manufacturer: Vishay-Dale; CompType: Resistor; Value: 2.55k; Res_ohm: 2550; Value_Code: 2k55; Tolerance_%: 1; Power_W: 0.1; Value2: 0.1W; VDC_V: 75; TempCo: 100 ppm/C; SizeArea_mm2: 1.28; SizeX_mm: 1.6; SizeY_mm: 0.8; EIA_Code: E96; U/M: EA; AEC Category: Q200; Green_Lifecycle: Active; Green_REACh: Passed
R108 = CRCW060352K3FKEA: RES, 52.3 k, 1%, 0.1 W, 0603; Manufacturer: Vishay-Dale; CompType: Resistor; Value: 52.3k; Res_ohm: 52300; Value_Code: 52k3; Tolerance_%: 1; Power_W: 0.1; Value2: 0.1W; VDC_V: 75; TempCo: 100 ppm/C; SizeArea_mm2: 1.28; SizeX_mm: 1.6; SizeY_mm: 0.8; EIA_Code: E96; U/M: EA; AEC Category: Q200; Green_Lifecycle: Active; Green_REACh: Passed
R109 R110 R113 = CRCW060310R0FKEA: RES, 10.0, 1%, 0.1 W, 0603; Manufacturer: Vishay-Dale; CompType: Resistor; Res_ohm: 10; Value_Code: 10R0; Tolerance_%: 1; Power_W: 0.1; Value2: 0.1W; VDC_V: 75; TempCo: 100 ppm/C; EIA_Code: E96; U/M: EA; AEC Category: Q200
R111 R114 = RC0603FR-071KL: RES, 1.00 k, 1%, 0.1 W, 0603; Manufacturer: Yageo America; CompType: Resistor; Value: 1.00k; Res_ohm: 1000; Value_Code: 1k00; Tolerance_%: 1; Power_W: 0.1; Value2: 0.1W; VDC_V: 150; TempCo: 200 ppm/C; SizeArea_mm2: 1.28; SizeX_mm: 1.6; SizeY_mm: 0.8; EIA_Code: E96; U/M: EA; AEC Category: Q200; Green_Lifecycle: Active; Green_REACh: Passed
R112 R124 = RC0603FR-07100KL: RES, 100 k, 1%, 0.1 W, 0603; Manufacturer: Yageo America; CompType: Resistor; Value: 100k; Res_ohm: 100000; Tolerance_%: 1; Power_W: 0.1; Value2: 0.1W; VDC_V: 150; TempCo: 200 ppm/C; SizeArea_mm2: 1.28; SizeX_mm: 1.6; SizeY_mm: 0.8; EIA_Code: E96; U/M: EA; AEC Category: Q200; Green_Lifecycle: Active; Green_REACh: Passed
R115 = RC0603FR-07442KL: RES, 442 k, 1%, 0.1 W, 0603; Manufacturer: Yageo America; CompType: Resistor; Value: 442k; Res_ohm: 442000; Tolerance_%: 1; Power_W: 0.1; Value2: 0.1W; VDC_V: 150; TempCo: 200 ppm/C; SizeArea_mm2: 1.28; SizeX_mm: 1.6; SizeY_mm: 0.8; EIA_Code: E96; U/M: EA; AEC Category: Q200; Green_Lifecycle: Active; Green_REACh: Passed
R116 = RT0603BRD07200KL: RES, 200 k, 0.1%, 0.1 W, 0603; Manufacturer: Yageo America; CompType: Resistor; Value: 200k; Res_ohm: 200000; Tolerance_%: 0.1; Value2: 0.1W; VDC_V: 75; TempCo: 25 ppm/C; SizeArea_mm2: 1.28; SizeX_mm: 1.6; SizeY_mm: 0.8; SizeZ_mm: 1; EIA_Code: E192; U/M: EA; AEC Category: Q200; Green_Lifecycle: Active; Green_REACh: Passed
R117 = RR0816P-4422-D-63C: RES, 44.2 k, 0.5%, 0.0625 W, 0603; Manufacturer: Susumu Co Ltd; CompType: Resistor; Value: 44.2k; Res_ohm: 44200; Value_Code: 44k2; Tolerance_%: 0.5; Power_W: 0.0625; VDC_V: 75; TempCo: 25 ppm/C; SizeArea_mm2: 1.3175; SizeX_mm: 1.55; SizeY_mm: 0.85; EIA_Code: E192; U/M: EA; AEC Category: Q200; AEC Qualified: N; Green_Lifecycle: Active; Green_REACh: Passed
R118 = RR0816P-104-D: RES, 100 k, 0.5%, 0.0625 W, 0603; Manufacturer: Susumu Co Ltd; CompType: Resistor; Value: 100k; Res_ohm: 100000; Tolerance_%: 0.5; Power_W: 0.0625; VDC_V: 75; TempCo: 25 ppm/C; SizeArea_mm2: 1.3175; SizeX_mm: 1.55; SizeY_mm: 0.85; EIA_Code: E192; U/M: EA; AEC Category: Q200; AEC Qualified: N; Green_Lifecycle: Active; Green_REACh: Passed
R119 R127 = RC0603JR-070RL: RES, 0, 5%, 0.1 W, 0603; Manufacturer: Yageo America; CompType: Resistor; Value: 0; Value_Code: 0000; Tolerance_%: 5; Power_W: 0.1; Value2: 0.1W; VDC_V: 50; TempCo: 200 ppm/C; SizeArea_mm2: 1.28; SizeX_mm: 1.6; SizeY_mm: 0.8; SizeZ_mm: 1; EIA_Code: E24; U/M: EA; AEC Category: Q200; Green_Lifecycle: Active; Green_REACh: Passed
R120 = RR0816P-8661-D-91H: RES, 8.66 k, 0.5%, 0.0625 W, 0603; Manufacturer: Susumu Co Ltd; CompType: Resistor; Value: 8.66k; Res_ohm: 8660; Value_Code: 8k66; Tolerance_%: 0.5; Power_W: 0.0625; VDC_V: 75; TempCo: 25 ppm/C; SizeArea_mm2: 1.3175; SizeX_mm: 1.55; SizeY_mm: 0.85; EIA_Code: E192; U/M: EA; AEC Category: Q200; AEC Qualified: N
R121 = RT0603DRE0732K4L: RES, 32.4 k, 0.5%, 0.1 W, 0603; Manufacturer: Yageo America; CompType: Resistor; Value: 32.4k; Res_ohm: 32400; Value_Code: 32k4; Tolerance_%: 0.5; Power_W: 0.1; Value2: 0.1W; VDC_V: 75; TempCo: 50 ppm/C; SizeArea_mm2: 1.28; SizeX_mm: 1.6; SizeY_mm: 0.8; SizeZ_mm: 1; EIA_Code: E192; U/M: EA; AEC Category: Q200
R122 = RC0603FR-0747KL: RES, 47.0 k, 1%, 0.1 W, 0603; Manufacturer: Yageo America; CompType: Resistor; Value: 47.0k; Res_ohm: 47000; Value_Code: 47k0; Tolerance_%: 1; Power_W: 0.1; Value2: 0.1W; VDC_V: 150; TempCo: 200 ppm/C; SizeArea_mm2: 1.28; SizeX_mm: 1.6; SizeY_mm: 0.8; U/M: EA; AEC Category: Q200; Green_Lifecycle: Active; Green_REACh: Passed
R123 = CRCW060324K9FKEA: RES, 24.9 k, 1%, 0.1 W, 0603; Manufacturer: Vishay-Dale; CompType: Resistor; Value: 24.9k; Res_ohm: 24900; Value_Code: 24k9; Tolerance_%: 1; Power_W: 0.1; Value2: 0.1W; VDC_V: 75; TempCo: 100 ppm/C; SizeArea_mm2: 1.28; SizeX_mm: 1.6; SizeY_mm: 0.8; EIA_Code: E96; U/M: EA; AEC Category: Q200; Green_Lifecycle: Active; Green_REACh: Passed
R128 = CRCW06031K00FKEA: RES, 1.00 k, 1%, 0.1 W, 0603; Manufacturer: Vishay-Dale; CompType: Resistor; Value: 1.00k; Res_ohm: 1000; Value_Code: 1k00; Tolerance_%: 1; Power_W: 0.1; Value2: 0.1W; VDC_V: 75; TempCo: 100 ppm/C; SizeArea_mm2: 1.28; SizeX_mm: 1.6; SizeY_mm: 0.8; EIA_Code: E96; U/M: EA; AEC Category: Q200; Green_Lifecycle: Active; Green_REACh: Passed
SH-J20 = 969102-0000-DA: Shunt, 100mil, Gold plated, Black; Manufacturer: 3M; Alternate Manufacturer: Samtec; Value: 1x2; Note: You can "mate" this to a header by matching the designator.  i.e. use SH-J3 for header J3; Green_Lifecycle: Active; Green_REACh: Passed
SH-J22 = 969102-0000-DA: Shunt, 100mil, Gold plated, Black; Manufacturer: 3M; Alternate Manufacturer: Samtec; Value: 1x2; Note: You can "mate" this to a header by matching the designator.  i.e. use SH-J3 for header J3
TP15-TP23 TP28 TP29 = TESTPOINT_PIGTAIL: PIGTAIL; Manufacturer: Texas Instruments; SymbolCreator: Altium
U27 = TPS26602PWPR: 60V 2A Industrial eFuse With Integrated Reverse-Input Polarity Protection, PWP0016H (TSSOP-16); Alternate PartNumber: TPS26602PWPT; Manufacturer: Texas Instruments; SymbolCreator: Altium; SizeArea_mm2: 32; SizeAreaWB_mm2: 58.8; SizeX_mm: 6.4; SizeY_mm: 5; SizeZ_mm: 1.2; CompType: IC; U/M: EA
U28 = DAC082S085CISD/NOPB: 8-Bit Micro Power DUAL Digital-to-Analog Converter with Rail-to-Rail Output, 10-pin LLP, Pb-Free; Manufacturer: Texas Instruments; PackageTopMarking: ZXYTT*X77C; PowerWise: Y; CompType: D/A Converter
U29 = LP5907MFX-3.3/NOPB: 250-mA Ultra-Low-Noise, Low-IQ LDO, DBV0005A (SOT-23-5); Manufacturer: Texas Instruments; SymbolCreator: a0799628; SizeArea_mm2: 8.12; SizeAreaWB_mm2: 14.82; SizeX_mm: 2.8; SizeY_mm: 2.9; SizeZ_mm: 1.45; CompType: IC; U/M: EA
U30 = REF3025AIDBZR: 2.5 V, 50 ppm / degC, 50 uA Series (Bandgap) Voltage Reference, -40 to 125 degC, 3-pin SOT-23 (DBZ), Green (RoHS & no Sb/Br); Manufacturer: Texas Instruments; Alternate PartNumber: Equivalent; Initial Accuracy @ 25/deg C(%): 0.2; Iq(Max)(uA): 50; Rating: Catalog; SubFamily: Series Voltage Reference; Temp Coeff(Typ)(ppm/ degree C): 20; VI(Max)(V): 5.5; VI(Min)(V): 2.501; VO(V): 2.5
U31 = LM5165DRCR: 3V-65V, 150mA Synchronous Buck Converter With Ultra-Low IQ, DRC0010J (VSON-10); Alternate PartNumber: LM5165DRCT; Manufacturer: Texas Instruments; SymbolCreator: Altium; SizeArea_mm2: 9; SizeAreaWB_mm2: 16; SizeX_mm: 3; SizeZ_mm: 1; CompType: IC; U/M: EA
U32 = TPS22810DRV: 12-V, 2-A, 65-mohm¸ On-Resistance Load Switch, DRV0006A (WSON-6); Manufacturer: Texas Instruments; SymbolCreator: Altium; SizeArea_mm2: 4; SizeAreaWB_mm2: 9; SizeX_mm: 2; SizeZ_mm: 0.8; CompType: IC; U/M: EA

## Sheet TIDA-01081E2_Controller.SchDoc: MCU
size 431 x 279 mm; Date: Not shown in title block; ApprovedBy: Not shown in title block; CheckedBy: Not shown in title block; Author: Not shown in title block; CompanyName: Not shown in title block; DrawnBy: SG; Engineer: Not shown in title block; Organization: Not shown in title block; Address1: Not shown in title block; Address2: Not shown in title block; Address3: Not shown in title block; Address4: Not shown in title block; DocumentNumber: 6; Revision: Use project parameter SCH_Rev; SheetNumber: 6; SheetTotal: 8; PageSetup: Record=PageOptions¦CenterHorizontal=True¦CenterVertical=True¦PrintScale=0.94¦XCorrection=1.00¦YCorrection=1.00¦PrintKind=0¦BorderSize=5000000¦LeftOffset=0¦BottomOffset=0¦Orientation=2¦PaperLength=4200¦PaperWidth=2970¦Scale=100¦PaperSource=7¦PrintQuality=600¦MediaType=1¦DitherType=10¦PrintScaleMode=1¦PaperKind=A3¦PaperIndex=8
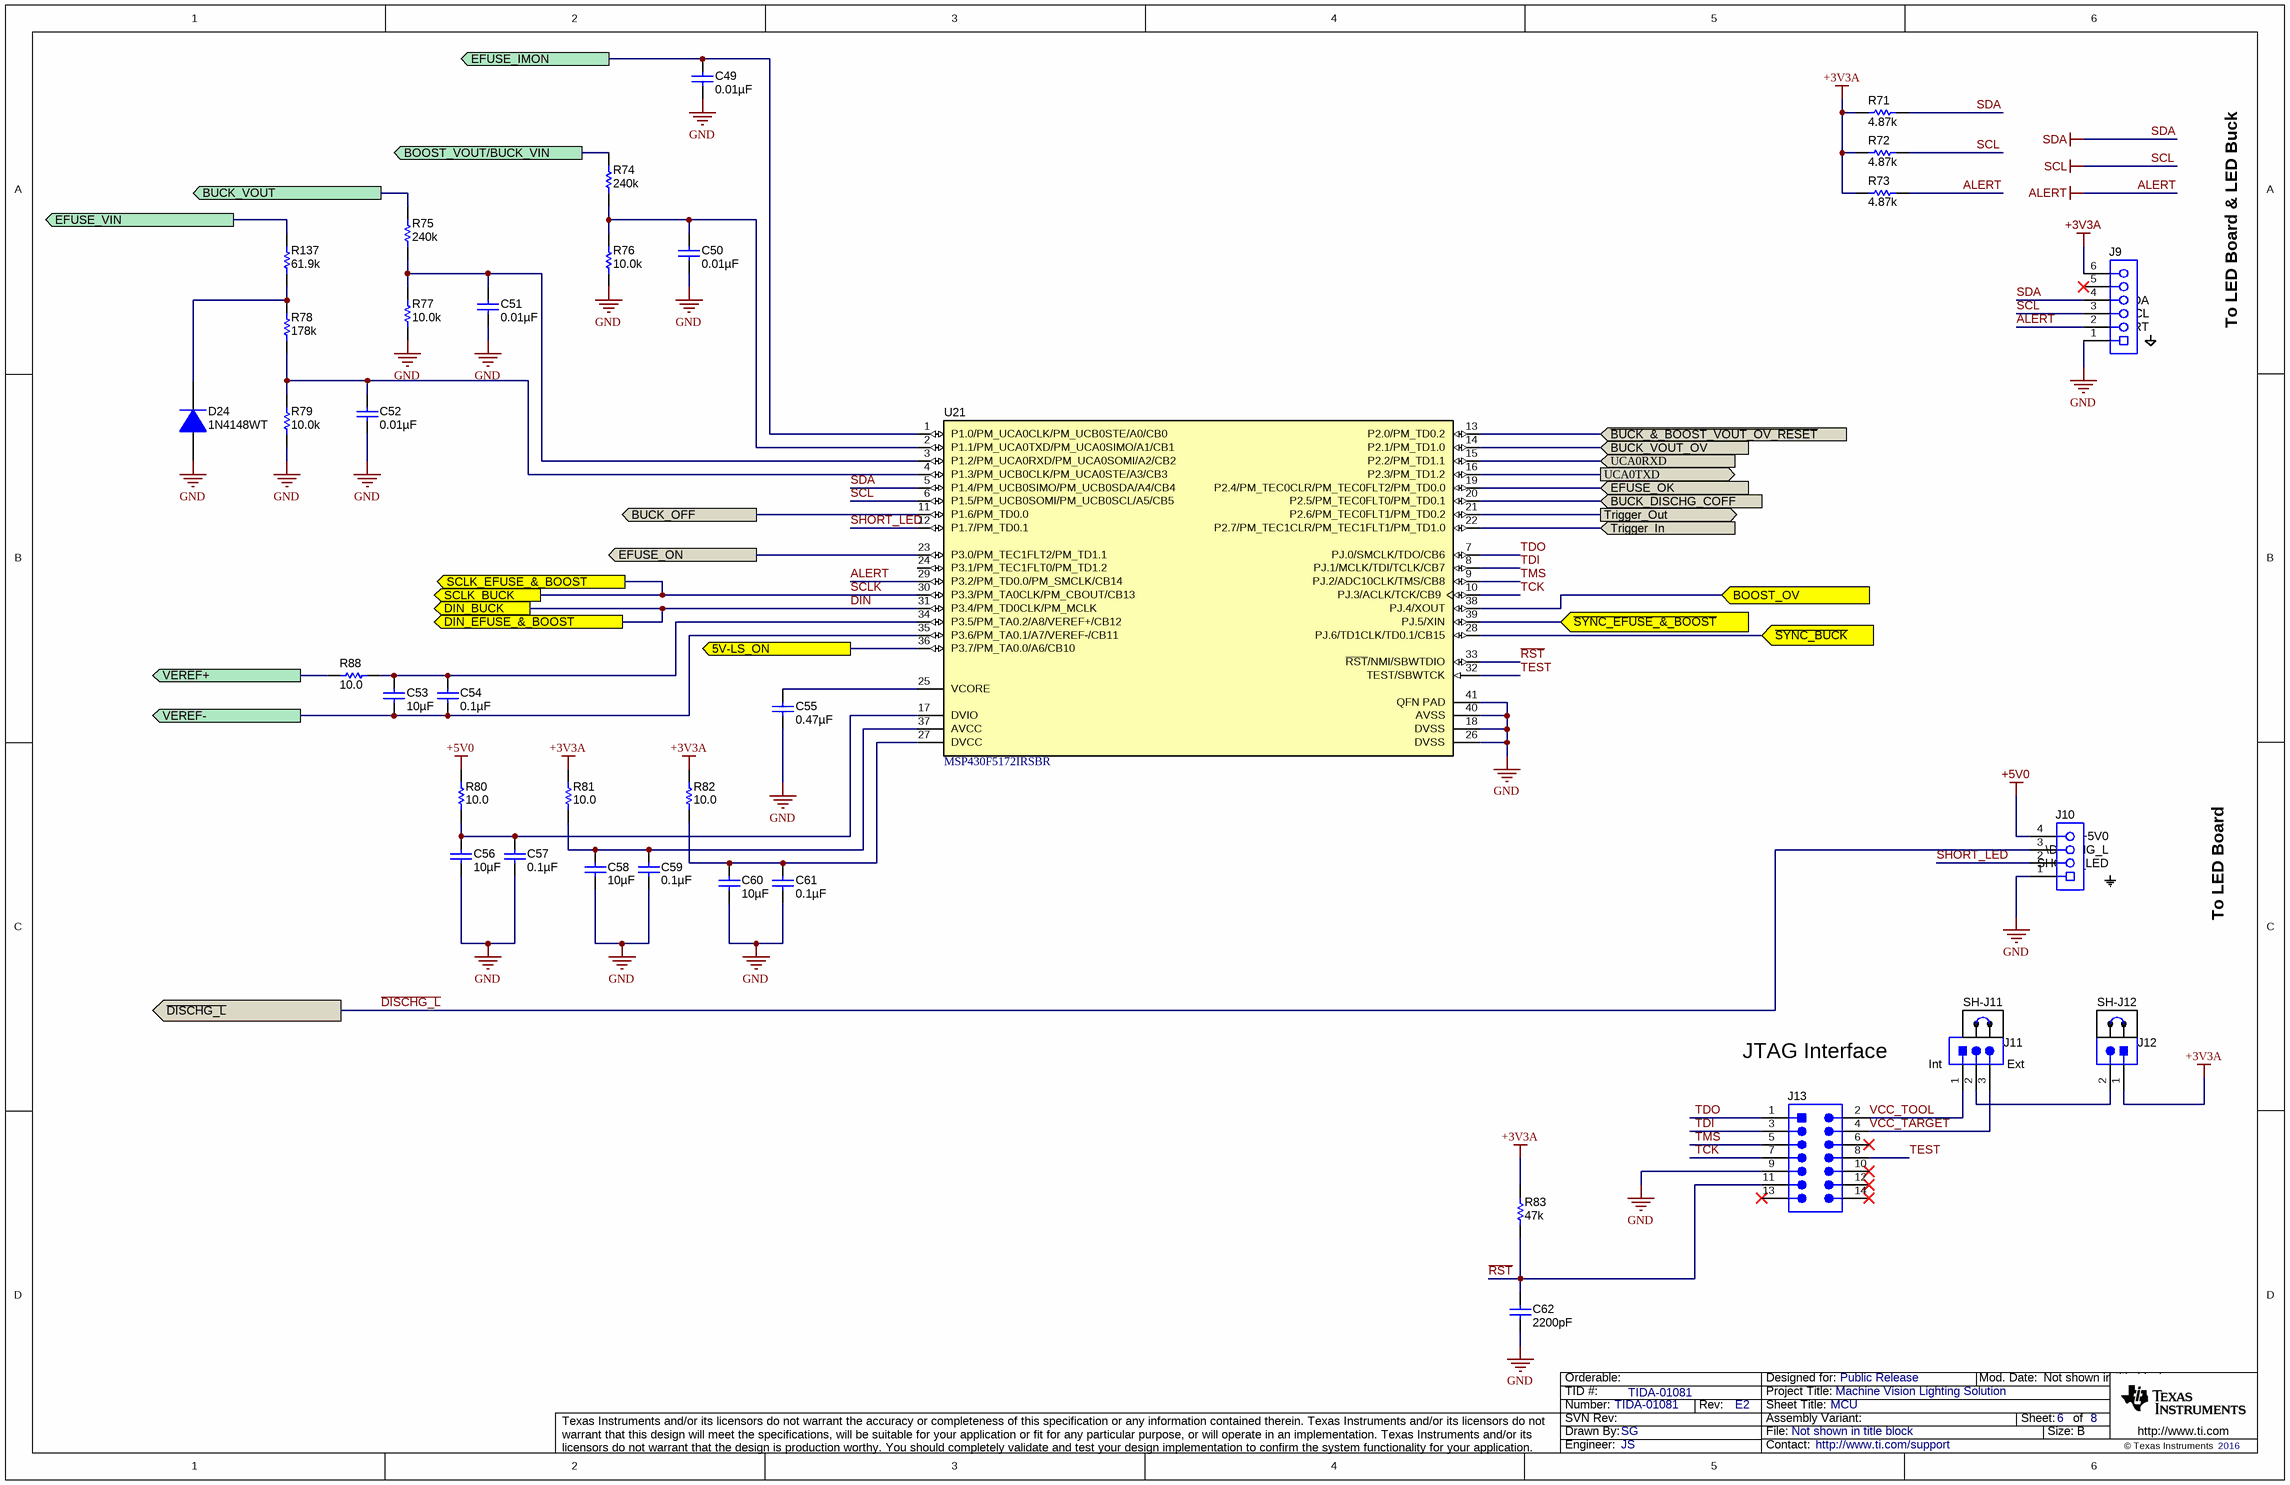
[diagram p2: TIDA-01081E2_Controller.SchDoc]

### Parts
C49  ValueDisplayed: 0.01µF  [0402]  (hidden comment: C1005X7R1C103K050BA)
C50  ValueDisplayed: 0.01µF  [0402]  (hidden comment: C1005X7R1C103K050BA)
C51  ValueDisplayed: 0.01µF  [0402]  (hidden comment: C1005X7R1C103K050BA)
C52  ValueDisplayed: 0.01µF  [0402]  (hidden comment: C1005X7R1C103K050BA)
C53  ValueDisplayed: 10µF  [0603]  (hidden comment: GRM188Z71A106MA73D)
C54  ValueDisplayed: 0.1µF  [0402]  (hidden comment: GRM155R71A104KA01D)
C55  ValueDisplayed: 0.47µF  [0603S]  (hidden comment: GRM188R70J474KA01D)
C56  ValueDisplayed: 10µF  [0603]  (hidden comment: GRM188Z71A106MA73D)
C57  ValueDisplayed: 0.1µF  [0402]  (hidden comment: GRM155R71A104KA01D)
C58  ValueDisplayed: 10µF  [0603]  (hidden comment: GRM188Z71A106MA73D)
C59  ValueDisplayed: 0.1µF  [0402]  (hidden comment: GRM155R71A104KA01D)
C60  ValueDisplayed: 10µF  [0603]  (hidden comment: GRM188Z71A106MA73D)
C61  ValueDisplayed: 0.1µF  [0402]  (hidden comment: GRM155R71A104KA01D)
C62  ValueDisplayed: 2200pF  [0402]  (hidden comment: GRM155R70J222KA01D)
D24  1N4148WT  [Fairchild_SOD-523F]
J9  PPPC061LFBN-RC  [Sullins_PPPC061LFBN-RC]  (value not drawn)
J10  PPPC041LFBN-RC  [Sullins_PPPC041LFBN-RC]  (value not drawn)
J11  61300311121  [WURTH_61300311121]  (value not drawn)
J12  61300211121  [WURTH_61300211121]  (value not drawn)
J13  SBH11-PBPC-D07-RA-BK  [Sullins_SBH11-PBPC-D07-RA-BK]  (value not drawn)
R71  ValueDisplayed: 4.87k  [0603]  (hidden comment: RC0603FR-074K87L)
R72  ValueDisplayed: 4.87k  [0603]  (hidden comment: RC0603FR-074K87L)
R73  ValueDisplayed: 4.87k  [0603]  (hidden comment: RC0603FR-074K87L)
R74  ValueDisplayed: 240k  [0402]  (hidden comment: CRCW0402240KFKED)
R75  ValueDisplayed: 240k  [0402]  (hidden comment: CRCW0402240KFKED)
R76  ValueDisplayed: 10.0k  [0402]  (hidden comment: CRCW040210K0FKED)
R77  ValueDisplayed: 10.0k  [0402]  (hidden comment: CRCW040210K0FKED)
R78  ValueDisplayed: 178k  [0603]  (hidden comment: RC0603FR-07178KL)
R79  ValueDisplayed: 10.0k  [0402]  (hidden comment: CRCW040210K0FKED)
R80  value 10.0  [0603]  (hidden comment: CRCW060310R0FKEA)
R81  value 10.0  [0603]  (hidden comment: CRCW060310R0FKEA)
R82  value 10.0  [0603]  (hidden comment: CRCW060310R0FKEA)
R83  ValueDisplayed: 47k  [0402]  (hidden comment: CRCW040247K0JNED)
R88  ValueDisplayed: 10.0  [0402]  (hidden comment: CRCW040210R0FKED)
R137  ValueDisplayed: 61.9k  [0603]  (hidden comment: RC0603FR-0761K9L)
SH-J11  969102-0000-DA  [SNT-100-BK-G]  (value not drawn)
SH-J12  969102-0000-DA  [SNT-100-BK-G]  (value not drawn)
U21  MSP430F5172IRSBR  [RSB0040B]

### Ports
5V-LS_ON, BOOST_OV, BOOST_VOUT/BUCK_VIN, BUCK_DISCHG_COFF, BUCK_OFF (out), BUCK_VOUT, BUCK_VOUT_OV, DIN_BUCK, DIN_EFUSE_&_BOOST, EFUSE_IMON, EFUSE_OK, EFUSE_ON, EFUSE_VIN, SCLK_BUCK, SCLK_EFUSE_&_BOOST, Trigger_In (in), Trigger_Out (out), UCA0RXD (in), UCA0TXD (out), VEREF+, VEREF-, ~{BUCK_&_BOOST_VOUT_OV_RESET}, ~{DISCHG_L}, ~{SYNC_BUCK}, ~{SYNC_EFUSE_&_BOOST}

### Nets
5V-LS_ON: U21.36(P3.7/PM_TA0.0/A6/CB10) ; port 5V-LS_ON
+2V5REF: R88.2 ; port VEREF+
+3V3A: J9.6 J12.1 R71.2 R72.2 R73.2 R81.2 R82.2 R83.2
+5V0: J10.4 R80.2
ALERT: J9.2 R73.1 U21.29(P3.2/PM_TD0.0/PM_SMCLK/CB14)
Boost_VOUT_OVP: U21.38(PJ.4/XOUT) ; port BOOST_OV
BUCK_DISCHG_COFF: U21.20(P2.5/PM_TEC0FLT0/PM_TD0.1) ; port BUCK_DISCHG_COFF
BUCK_VOUT: R75.2 ; port BUCK_VOUT
GND: C49.2 C50.2 C51.2 C52.2 C53.2 C54.1 C55.2 C56.2 C57.1 C58.2 C59.1 C60.2 C61.1 C62.2 D24.2(A) J9.1 J10.1 J13.9 R76.1 R77.1 R79.1 U21.18(DVSS) U21.26(DVSS) U21.35(P3.6/PM_TA0.1/A7/VEREF-/CB11) U21.40(AVSS) U21.41(QFN_PAD) ; port VEREF-
SCL: J9.3 R72.1 U21.6(P1.5/PM_UCB0SOMI/PM_UCB0SCL/A5/CB5)
SDA: J9.4 R71.1 U21.5(P1.4/PM_UCB0SIMO/PM_UCB0SDA/A4/CB4)
~{BUCK_&_BOOST_VOUT_OV_RESET}: U21.13(P2.0/PM_TD0.2) ; port ~{BUCK_&_BOOST_VOUT_OV_RESET}
~{DISCHG_L}: J10.3 ; port ~{DISCHG_L}
~{RST}: C62.1 J13.11 R83.1 U21.33(~{RST}/NMI/SBWTDIO)
~{SYNC_BUCK}: U21.28(PJ.6/TD1CLK/TD0.1/CB15) ; port ~{SYNC_BUCK}
~{SYNC_EFUSE_&_BOOST}: U21.39(PJ.5/XIN) ; port ~{SYNC_EFUSE_&_BOOST}
BOOST_VOUT/BUCK_VIN: R74.2 ; port BOOST_VOUT/BUCK_VIN
BUCK_OFF: U21.11(P1.6/PM_TD0.0) ; port BUCK_OFF
BUCK_VOUT_OV: U21.14(P2.1/PM_TD1.0) ; port BUCK_VOUT_OV
DIN: U21.31(P3.4/PM_TD0CLK/PM_MCLK) ; port DIN_BUCK, port DIN_EFUSE_&_BOOST
EFUSE_IMON: C49.1 U21.1(P1.0/PM_UCA0CLK/PM_UCB0STE/A0/CB0) ; port EFUSE_IMON
EFUSE_OK: U21.19(P2.4/PM_TEC0CLR/PM_TEC0FLT2/PM_TD0.0) ; port EFUSE_OK
EFUSE_ON: U21.23(P3.0/PM_TEC1FLT2/PM_TD1.1) ; port EFUSE_ON
EFUSE_VIN: R137.2 ; port EFUSE_VIN
SCLK: U21.30(P3.3/PM_TA0CLK/PM_CBOUT/CB13) ; port SCLK_BUCK, port SCLK_EFUSE_&_BOOST
SHORT_LED: J10.2 U21.12(P1.7/PM_TD0.1)
TCK: J13.7 U21.10(PJ.3/ACLK/TCK/CB9)
TDI: J13.3 U21.8(PJ.1/MCLK/TDI/TCLK/CB7)
TDO: J13.1 U21.7(PJ.0/SMCLK/TDO/CB6)
TEST: J13.8 U21.32(TEST/SBWTCK)
TMS: J13.5 U21.9(PJ.2/ADC10CLK/TMS/CB8)
Trigger_In: U21.22(P2.7/PM_TEC1CLR/PM_TEC1FLT1/PM_TD1.0) ; port Trigger_In
Trigger_Out: U21.21(P2.6/PM_TEC0FLT1/PM_TD0.2) ; port Trigger_Out
UCA0RXD: U21.15(P2.2/PM_TD1.1) ; port UCA0RXD
UCA0TXD: U21.16(P2.3/PM_TD1.2) ; port UCA0TXD
VCC_TARGET: J11.3 J13.4
VCC_TOOL: J11.1 J13.2
NetC50_1: C50.1 R74.1 R76.2 U21.2(P1.1/PM_UCA0TXD/PM_UCA0SIMO/A1/CB1)
NetC51_1: C51.1 R75.1 R77.2 U21.3(P1.2/PM_UCA0RXD/PM_UCA0SOMI/A2/CB2)
NetC52_1: C52.1 R78.1 R79.2 U21.4(P1.3/PM_UCB0CLK/PM_UCA0STE/A3/CB3)
NetC53_1: C53.1 C54.2 R88.1 U21.34(P3.5/PM_TA0.2/A8/VEREF+/CB12)
NetC55_1: C55.1 U21.25(VCORE)
NetC56_1: C56.1 C57.2 R80.1 U21.17(DVIO)
NetC58_1: C58.1 C59.2 R81.1 U21.37(AVCC)
NetC60_1: C60.1 C61.2 R82.1 U21.27(DVCC)
NetD24_1: D24.1(K) R78.2 R137.1
NetJ11_2: J11.2 J12.2

Not connected (* = marked no-connect by the designer): J9 5*; J13 6* 10* 12* 13* 14*; U21 24(P3.1/PM_TEC1FLT0/PM_TD1.2)

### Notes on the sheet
- To LED Board & LED Buck
- (near J9) SDA
- (near J9) SCL
- (near J9) ALERT
- +5V0
- SHORT_LED
- \DISCHG_L
- To LED Board
- JTAG Interface
- (near J11) Int
- (near J11) Ext

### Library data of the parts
C49-C52 = C1005X7R1C103K050BA: as C15 on sheet TIDA-01081E2_CommonPower
C53 C56 C58 C60 = GRM188Z71A106MA73D: CAP, CERM, 10 µF, 10 V, +/- 20%, X7R, 0603; Manufacturer: MuRata; Polarized: N; CompType: Capacitor; Value: 10uF; U/M: EA; Cap_F: 0.00001; Tolerance_%: 20; Value1: Unknown; VDC_V: 10; Value2: 10V; TaMin_C: -55; TaMax_C: 125; SizeArea_mm2: 1.28; SizeAreaWB_mm2: 4.68; SizeX_mm: 1.6; SizeY_mm: 0.8; SizeZ_mm: 1; AEC Category: Q200; Green_Lifecycle: Active; Green_REACh: Passed
C54 C57 C59 C61 = GRM155R71A104KA01D: CAP, CERM, 0.1 µF, 10 V, +/- 10%, X7R, 0402; Manufacturer: MuRata; Polarized: N; CompType: Capacitor; Value: 0.1uF; U/M: EA; Cap_F: 0.0000001; Tolerance_%: 10; Value1: Unknown; Value2: 10V; TaMin_C: -55; TaMax_C: 125; AEC Category: Q200
C55 = GRM188R70J474KA01D: CAP, CERM, 0.47 µF, 6.3 V, +/- 10%, X7R, 0603; Manufacturer: MuRata; Polarized: N; CompType: Capacitor; Value: 0.47uF; U/M: EA; Cap_F: 0.00000047; Tolerance_%: 10; Value1: Unknown; VDC_V: 6.3; Value2: 6.3V; TaMin_C: -55; TaMax_C: 125; Cap_Case: 0603; AEC Category: Q200
C62 = GRM155R70J222KA01D: CAP, CERM, 2200 pF, 6.3 V, +/- 10%, X7R, 0402; Manufacturer: MuRata; Polarized: N; CompType: Capacitor; Value: 2200pF; U/M: EA; Cap_F: 0.0000000022; Tolerance_%: 10; Value1: Unknown; VDC_V: 6.3; Value2: 6.3V; TaMin_C: -55; TaMax_C: 125; AEC Category: Q200
D24 = 1N4148WT: as D21 on sheet TIDA-01081E2_CommonPower
J9 = PPPC061LFBN-RC: Receptacle, 2.54mm, 6x1, Gold, TH; Manufacturer: Sullins Connector Solutions; SymbolCreator: a0411947; Pitch_mm: 2.54; Gender: Female; Row_Count: 1; Current_A: 3; Voltage_V: 250; Cert_UL: Y
J10 = PPPC041LFBN-RC: Receptacle, 2.54mm, 4x1, Gold, TH; Manufacturer: Sullins Connector Solutions; SymbolCreator: a0411947; Pitch_mm: 2.54; Gender: Female; Row_Count: 1; Current_A: 3; Voltage_V: 250; Cert_UL: Y
J11 = 61300311121: Header, 2.54 mm, 3x1, Gold, TH; Manufacturer: Wurth Elektronik; SymbolCreator: a0799628; U/M: EA
J12 = 61300211121: Header, 2.54 mm, 2x1, Gold, TH; Manufacturer: Wurth Elektronik; SymbolCreator: a0412235; U/M: EA
J13 = SBH11-PBPC-D07-RA-BK: Header (Shrouded), 2.54 mm, 7x2, Gold, R/A, TH; Manufacturer: Sullins Connector Solutions; SymbolCreator: a0412235; U/M: EA
R71-R73 = RC0603FR-074K87L: RES, 4.87 k, 1%, 0.1 W, 0603; Manufacturer: Yageo America; CompType: Resistor; Value: 4.87k; Res_ohm: 4870; Value_Code: 4k87; Tolerance_%: 1; Power_W: 0.1; Value2: 0.1W; VDC_V: 150; TempCo: 200 ppm/C; SizeArea_mm2: 1.28; SizeX_mm: 1.6; SizeY_mm: 0.8; EIA_Code: E96; U/M: EA; AEC Category: Q200; Green_Lifecycle: Active; Green_REACh: Passed
R74 R75 = CRCW0402240KFKED: RES, 240 k, 1%, 0.063 W, 0402; Manufacturer: Vishay-Dale; CompType: Resistor; Value: 240k; Res_ohm: 240000; Tolerance_%: 1; Power_W: 0.063; Value2: 0.063W; VDC_V: 50; TempCo: 100 ppm/C; SizeArea_mm2: 0.5; SizeZ_mm: 0.6; U/M: EA; AEC Category: Q200
R76 R77 R79 = CRCW040210K0FKED: RES, 10.0 k, 1%, 0.063 W, 0402; Manufacturer: Vishay-Dale; CompType: Resistor; Value: 10.0k; Res_ohm: 10000; Value_Code: 10k0; Tolerance_%: 1; Power_W: 0.063; Value2: 0.063W; VDC_V: 50; TempCo: 100 ppm/C; SizeArea_mm2: 0.5; SizeZ_mm: 0.6; EIA_Code: E96; U/M: EA; AEC Category: Q200
R78 = RC0603FR-07178KL: RES, 178 k, 1%, 0.1 W, 0603; Manufacturer: Yageo America; CompType: Resistor; Value: 178k; Res_ohm: 178000; Tolerance_%: 1; Power_W: 0.1; Value2: 0.1W; VDC_V: 150; TempCo: 200 ppm/C; SizeArea_mm2: 1.28; SizeX_mm: 1.6; SizeY_mm: 0.8; EIA_Code: E96; U/M: EA; AEC Category: Q200; Green_Lifecycle: Active; Green_REACh: Passed
R80-R82 = CRCW060310R0FKEA: as R109 on sheet TIDA-01081E2_CommonPower
R83 = CRCW040247K0JNED: RES, 47 k, 5%, 0.063 W, 0402; Manufacturer: Vishay-Dale; CompType: Resistor; Value: 47k; Res_ohm: 47000; Value_Code: 47k0; Tolerance_%: 5; Power_W: 0.063; Value2: 0.063W; VDC_V: 50; TempCo: 200 ppm/C; EIA_Code: E24; U/M: EA; AEC Category: Q200
R88 = CRCW040210R0FKED: RES, 10.0, 1%, 0.063 W, 0402; Manufacturer: Vishay-Dale; CompType: Resistor; Value: 10.0; Res_ohm: 10; Value_Code: 10R0; Tolerance_%: 1; Power_W: 0.063; Value2: 0.063W; VDC_V: 50; TempCo: 100 ppm/C; EIA_Code: E96; U/M: EA; AEC Category: Q200; SizeArea_mm2: 0.5; SizeZ_mm: 0.6; Green_Lifecycle: Active; Green_REACh: Passed
R137 = RC0603FR-0761K9L: RES, 61.9 k, 1%, 0.1 W, 0603; Manufacturer: Yageo America; CompType: Resistor; Value: 61.9k; Res_ohm: 61900; Value_Code: 61k9; Tolerance_%: 1; Power_W: 0.1; Value2: 0.1W; VDC_V: 150; TempCo: 200 ppm/C; SizeArea_mm2: 1.28; SizeX_mm: 1.6; SizeY_mm: 0.8; EIA_Code: E96; U/M: EA; AEC Category: Q200
SH-J11 SH-J12 = 969102-0000-DA: as SH-J22 on sheet TIDA-01081E2_CommonPower
U21 = MSP430F5172IRSBR: 25 MHz Mixed Signal Microcontroller with 32 KB Flash, 2048 B SRAM and 29 GPIOs, -40 to 85 degC, 40-pin QFN (RSB), Green (RoHS & no Sb/Br); Alternate Manufacturer: Texas Instruments; Alternate PartNumber: Equivalent; ADC: 10-bit SAR; ADC Channels: 8; Brown Out Reset: Yes; DMA: 3; Flash(KB): 32; Frequency(MHz): 25; GPIO: 29; Multiplier: 32x32; Pin/Package: 38TSSOP, 40WQFN; SRAM(B): 2048; SubFamily: 5 Series; Timers - 16-bit: 2; USCI_A (UART/LIN/IrDA/SPI): 1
